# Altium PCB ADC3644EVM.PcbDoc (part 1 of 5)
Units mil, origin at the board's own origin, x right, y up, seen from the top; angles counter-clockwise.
Board outline 3900 x 2716.54 mil, 10 copper layers (Top Layer, L2 GND, L3 PWR, L4 GND, L5 SIG, L6 GND, L7 GND, L8 PWR, L9 GND, Bottom Layer), stack 61.2 mil thick; 368 components, 252 nets, 1539 pads, 1019 vias.
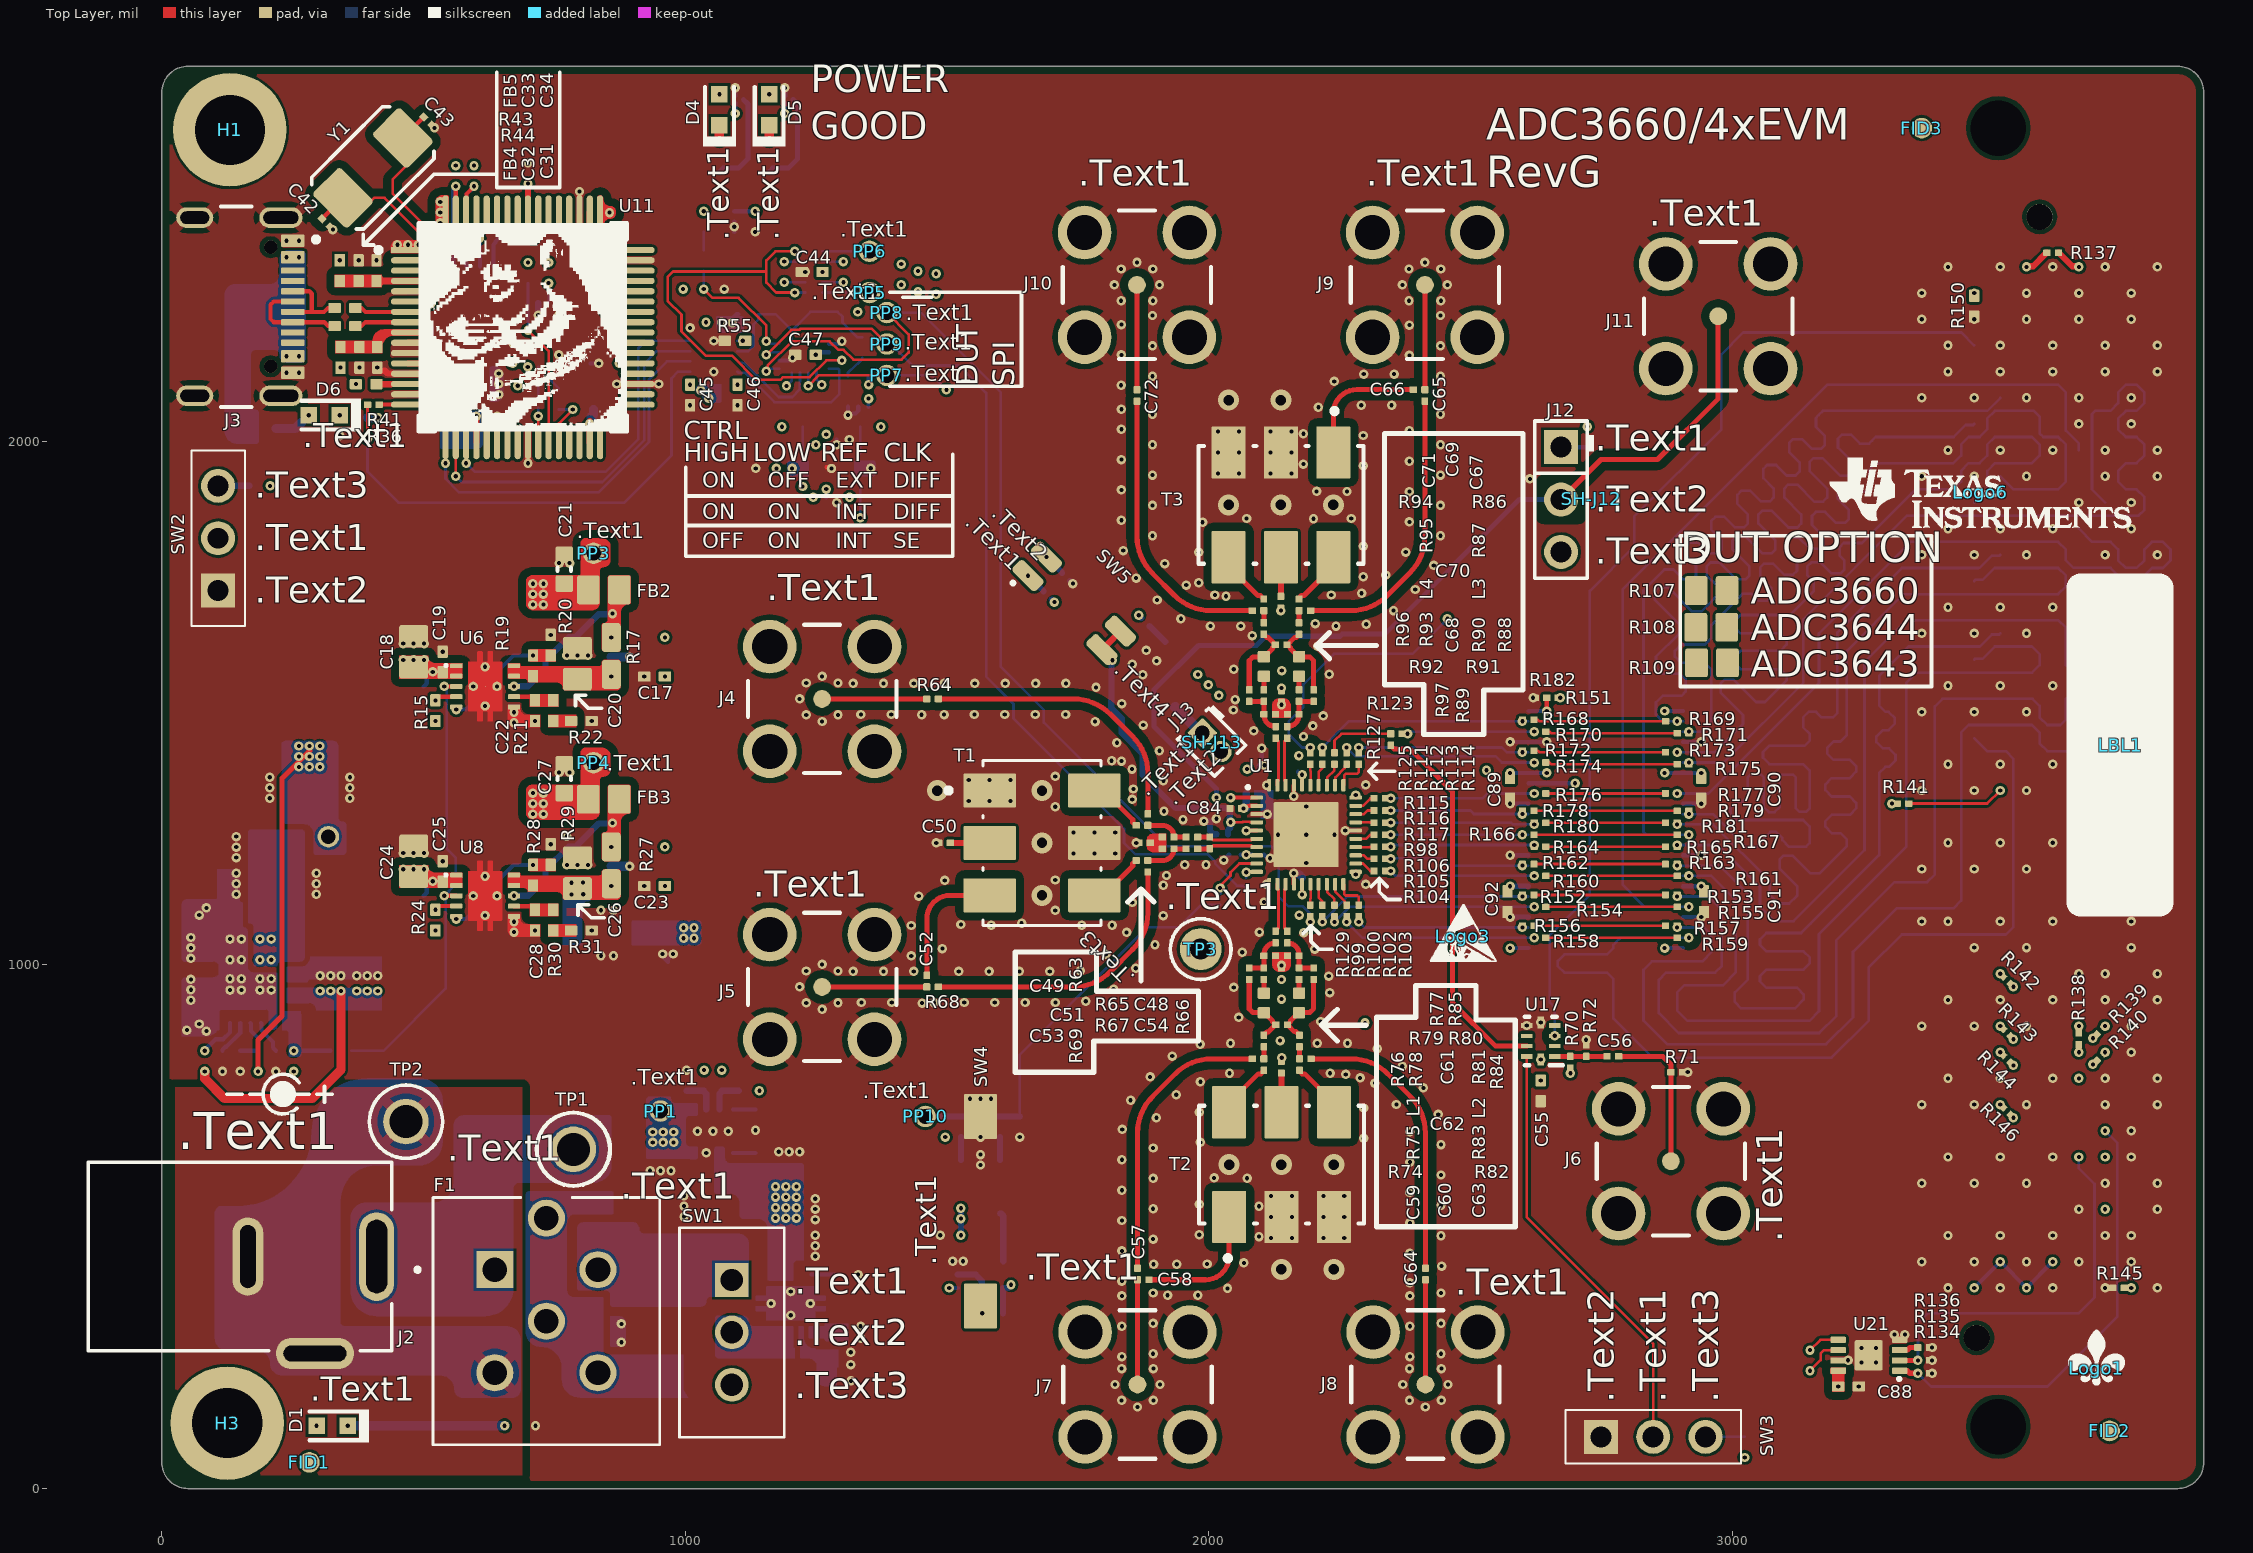
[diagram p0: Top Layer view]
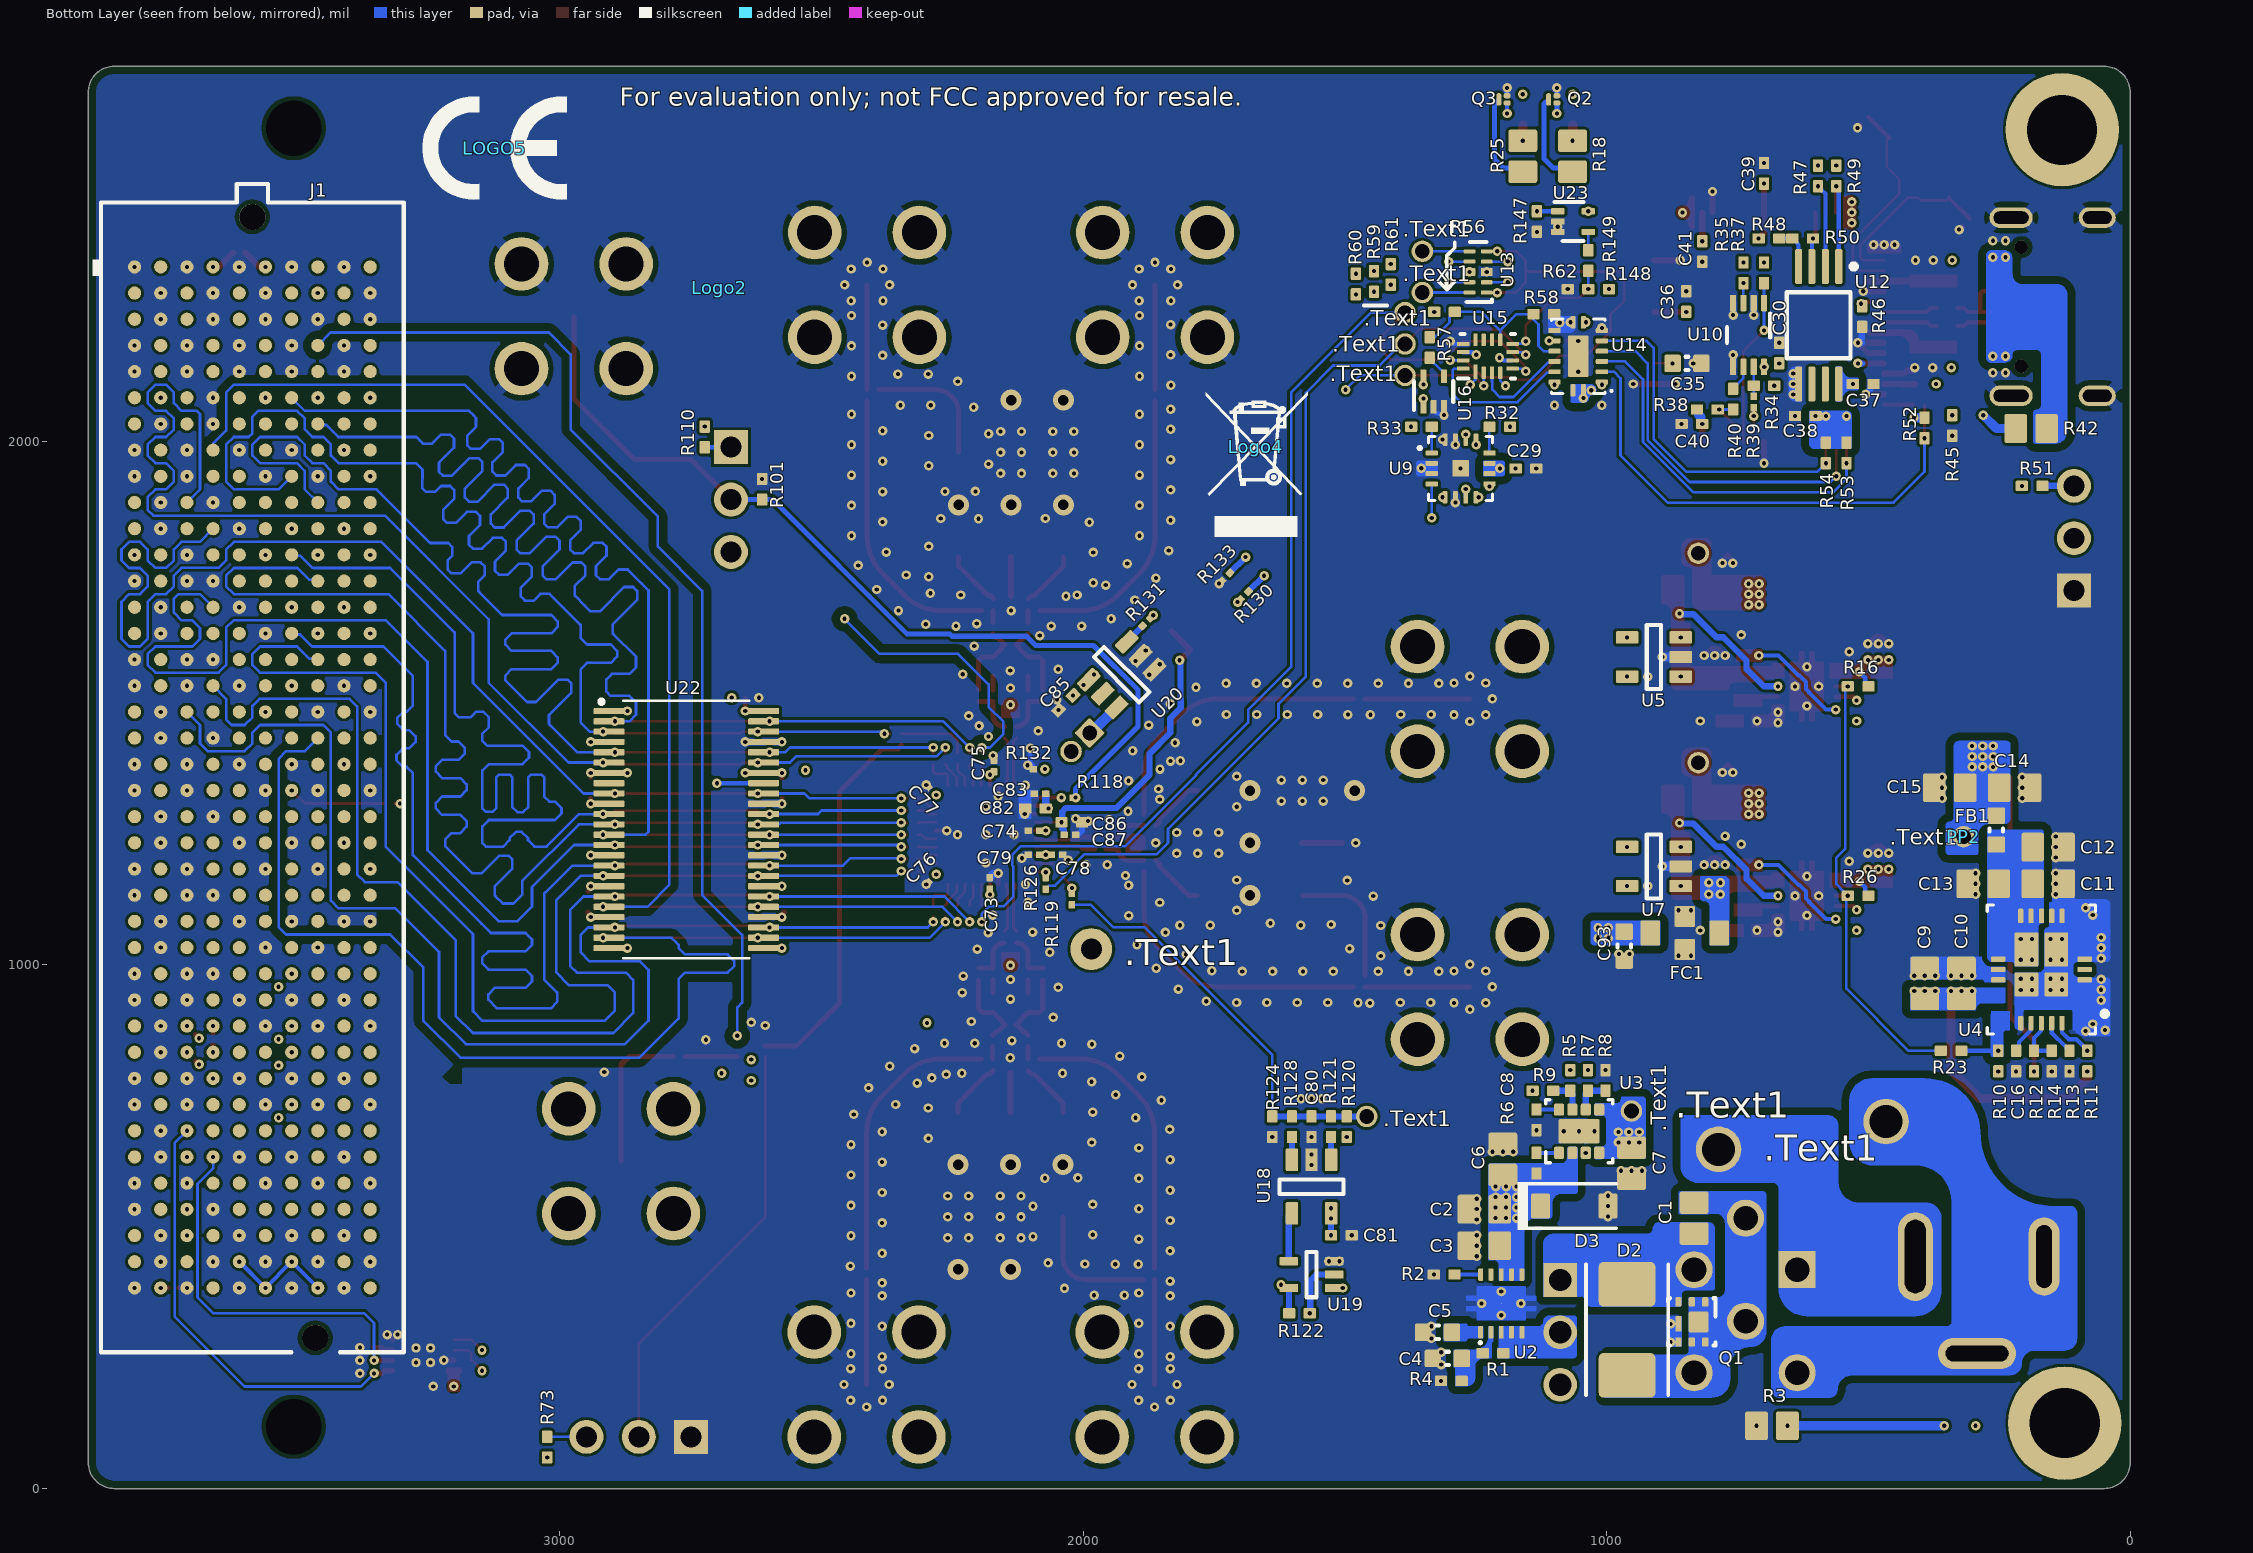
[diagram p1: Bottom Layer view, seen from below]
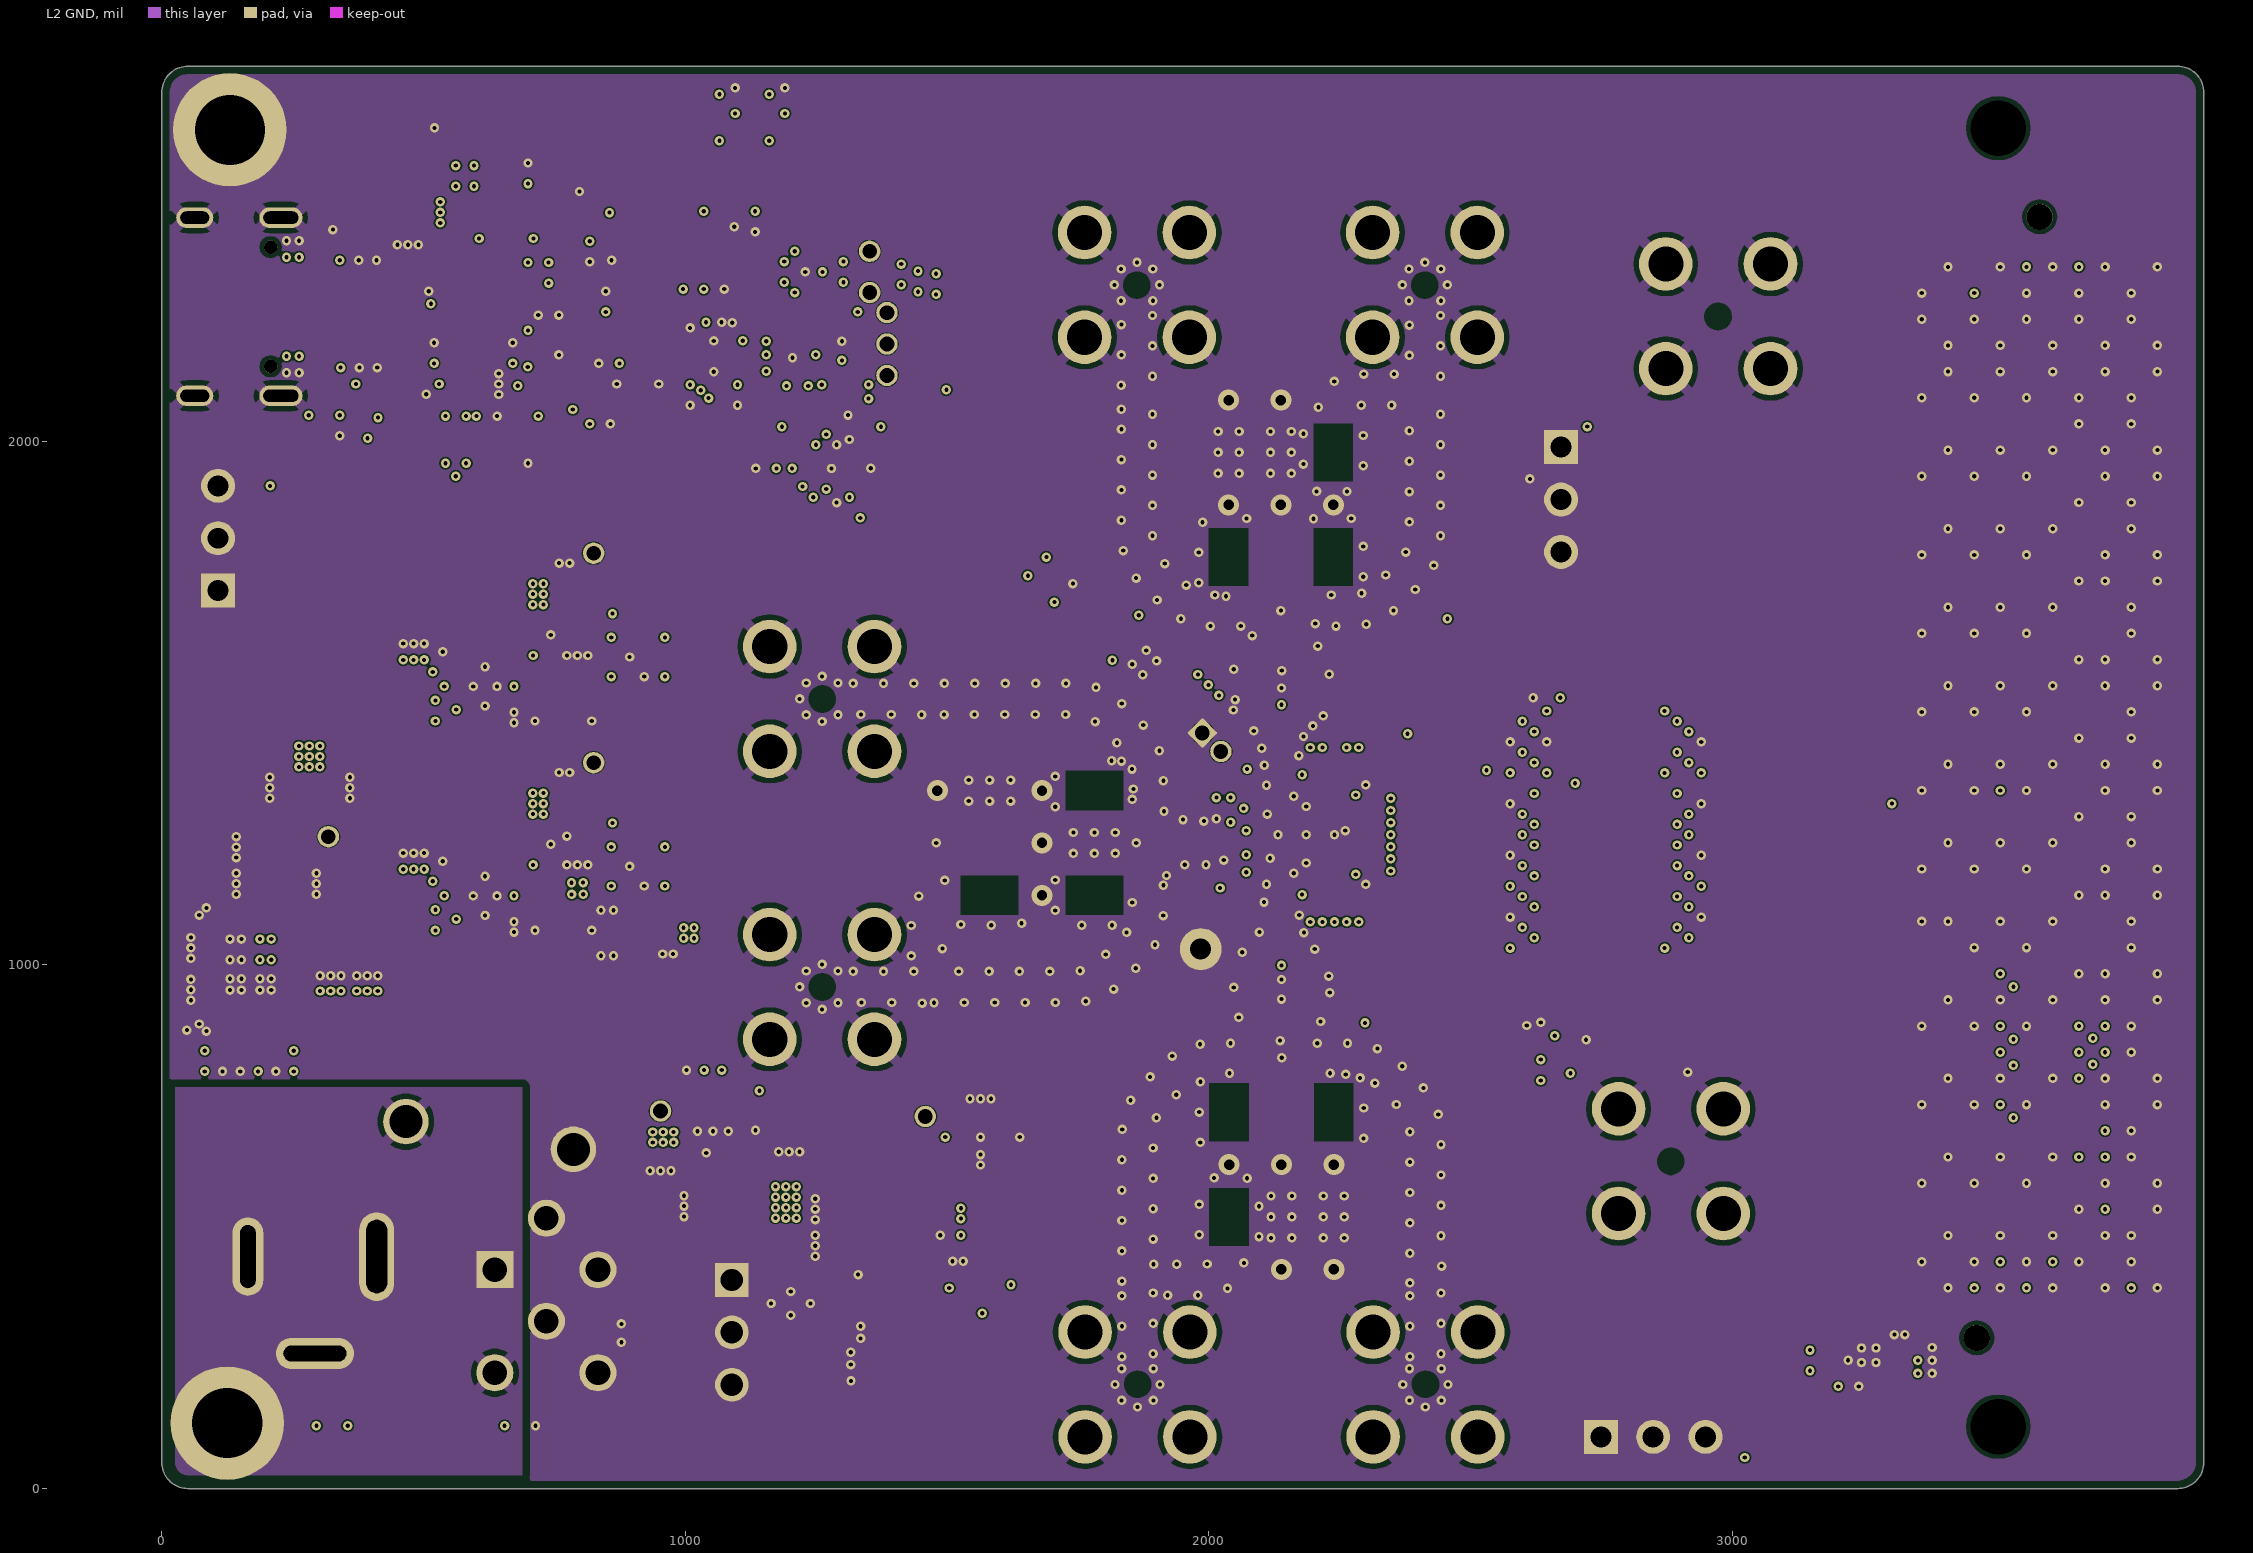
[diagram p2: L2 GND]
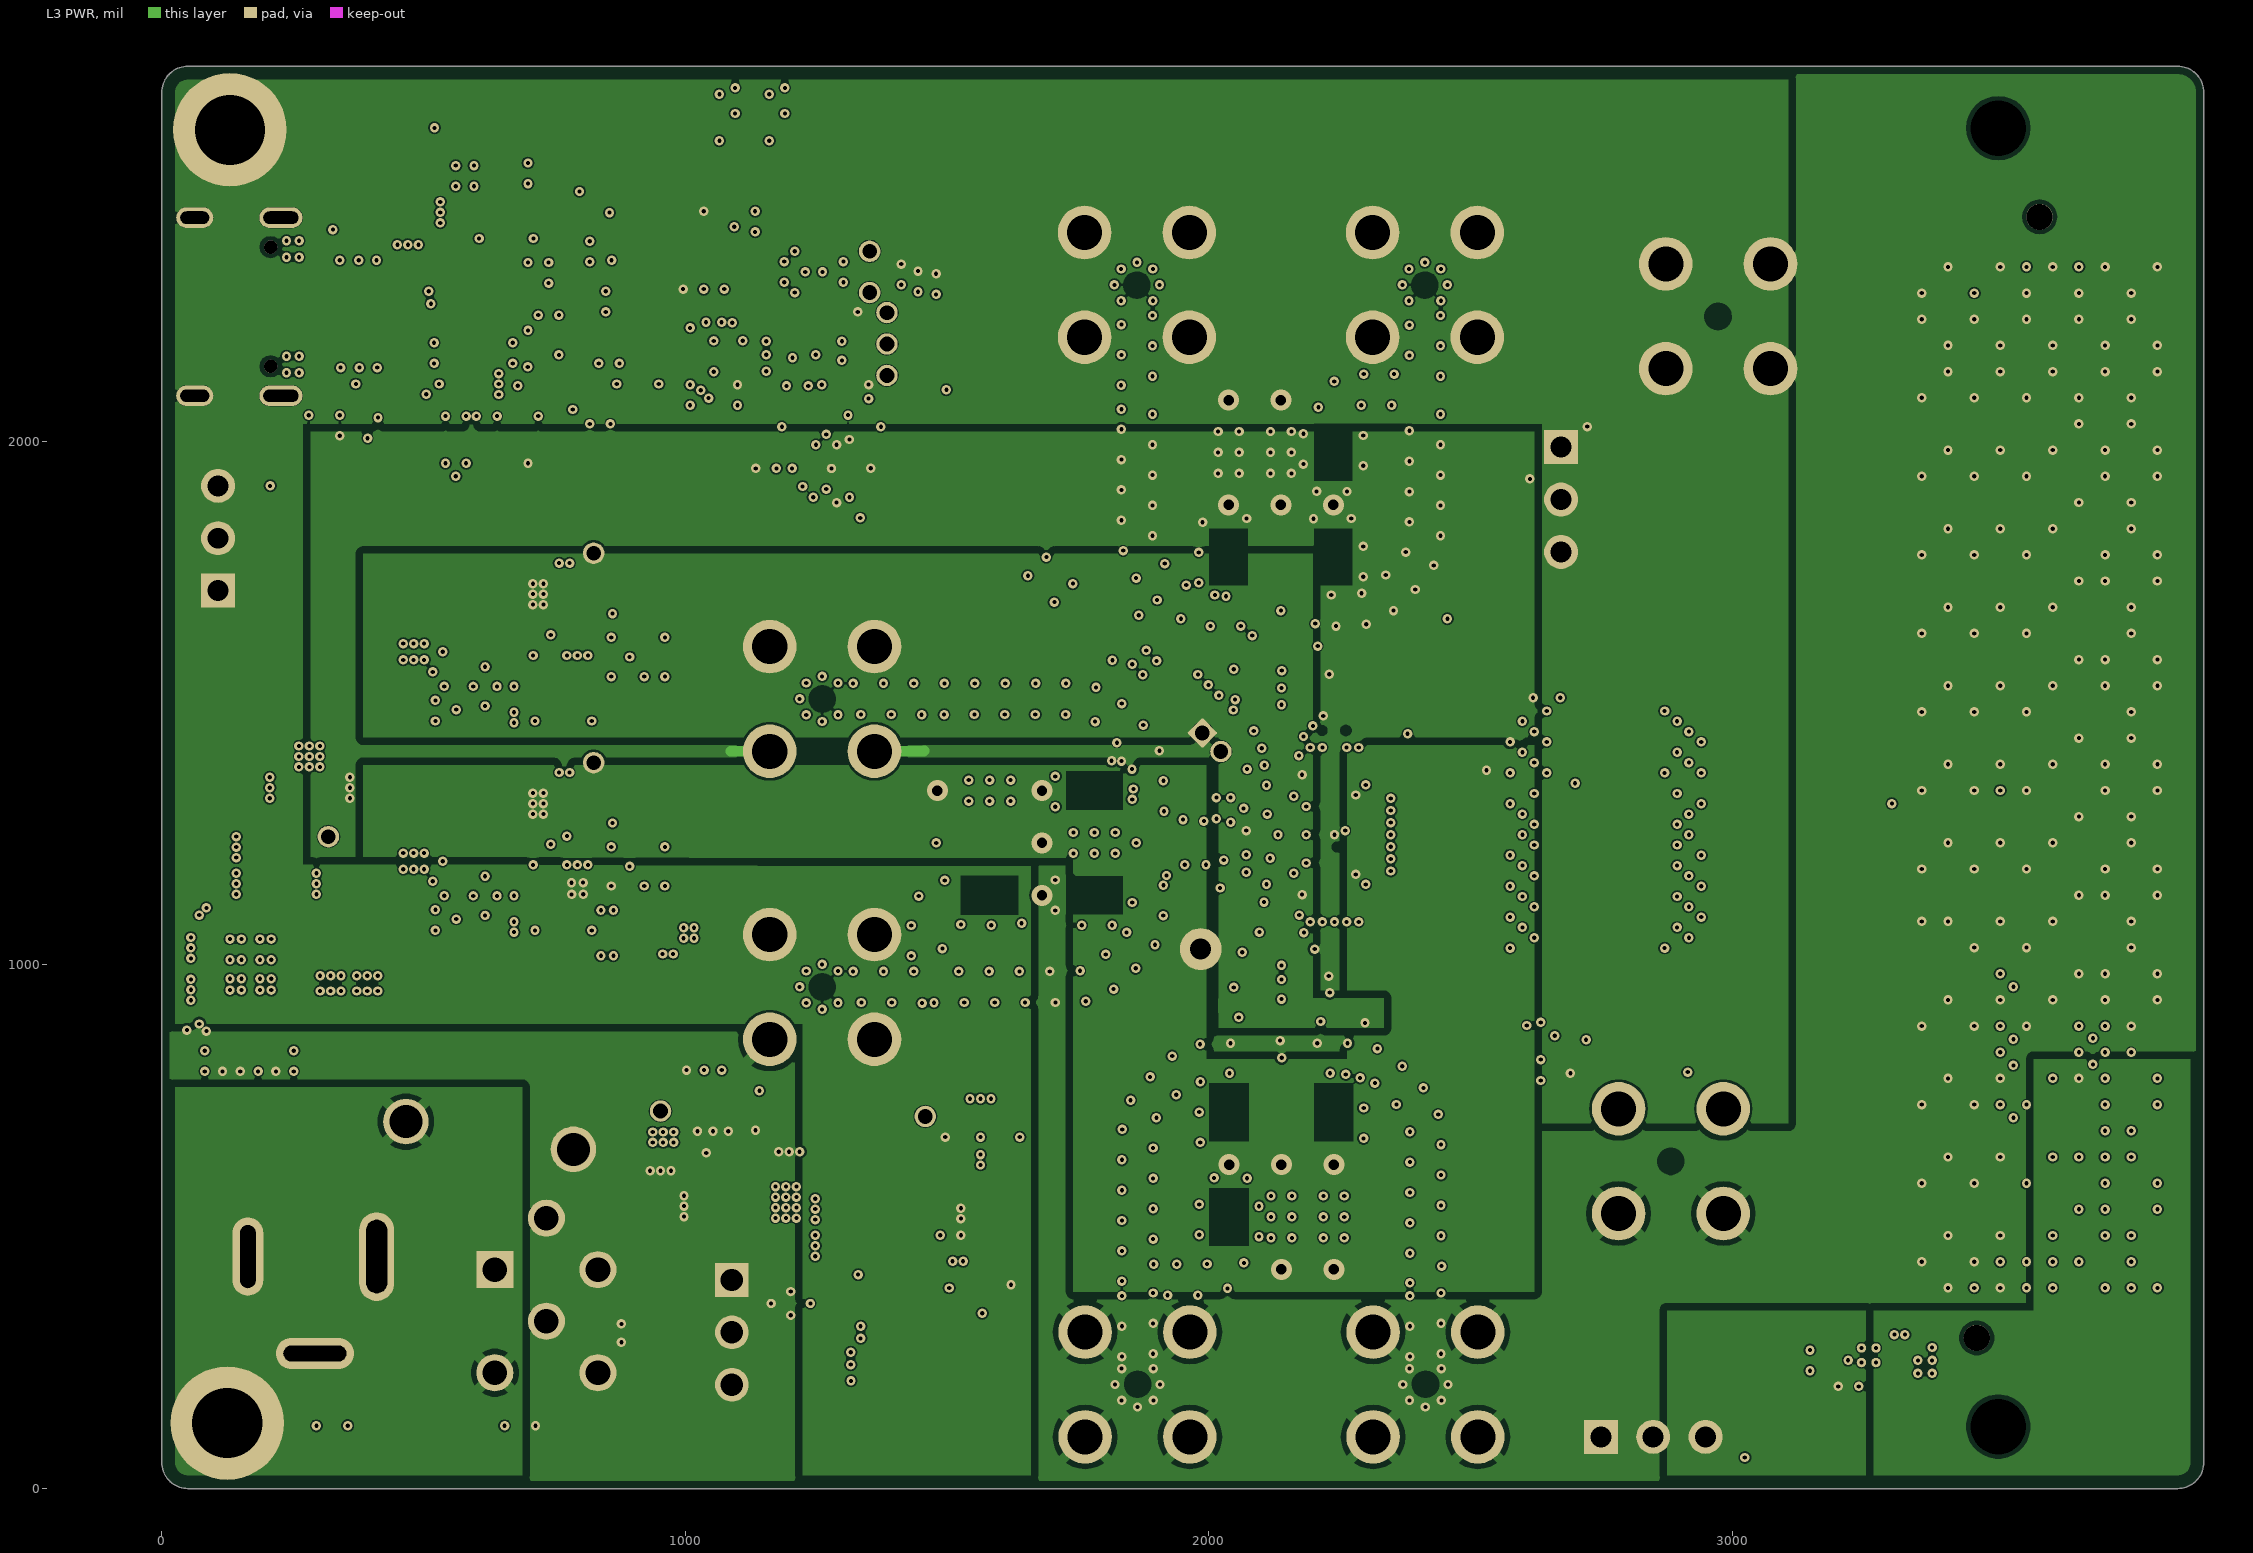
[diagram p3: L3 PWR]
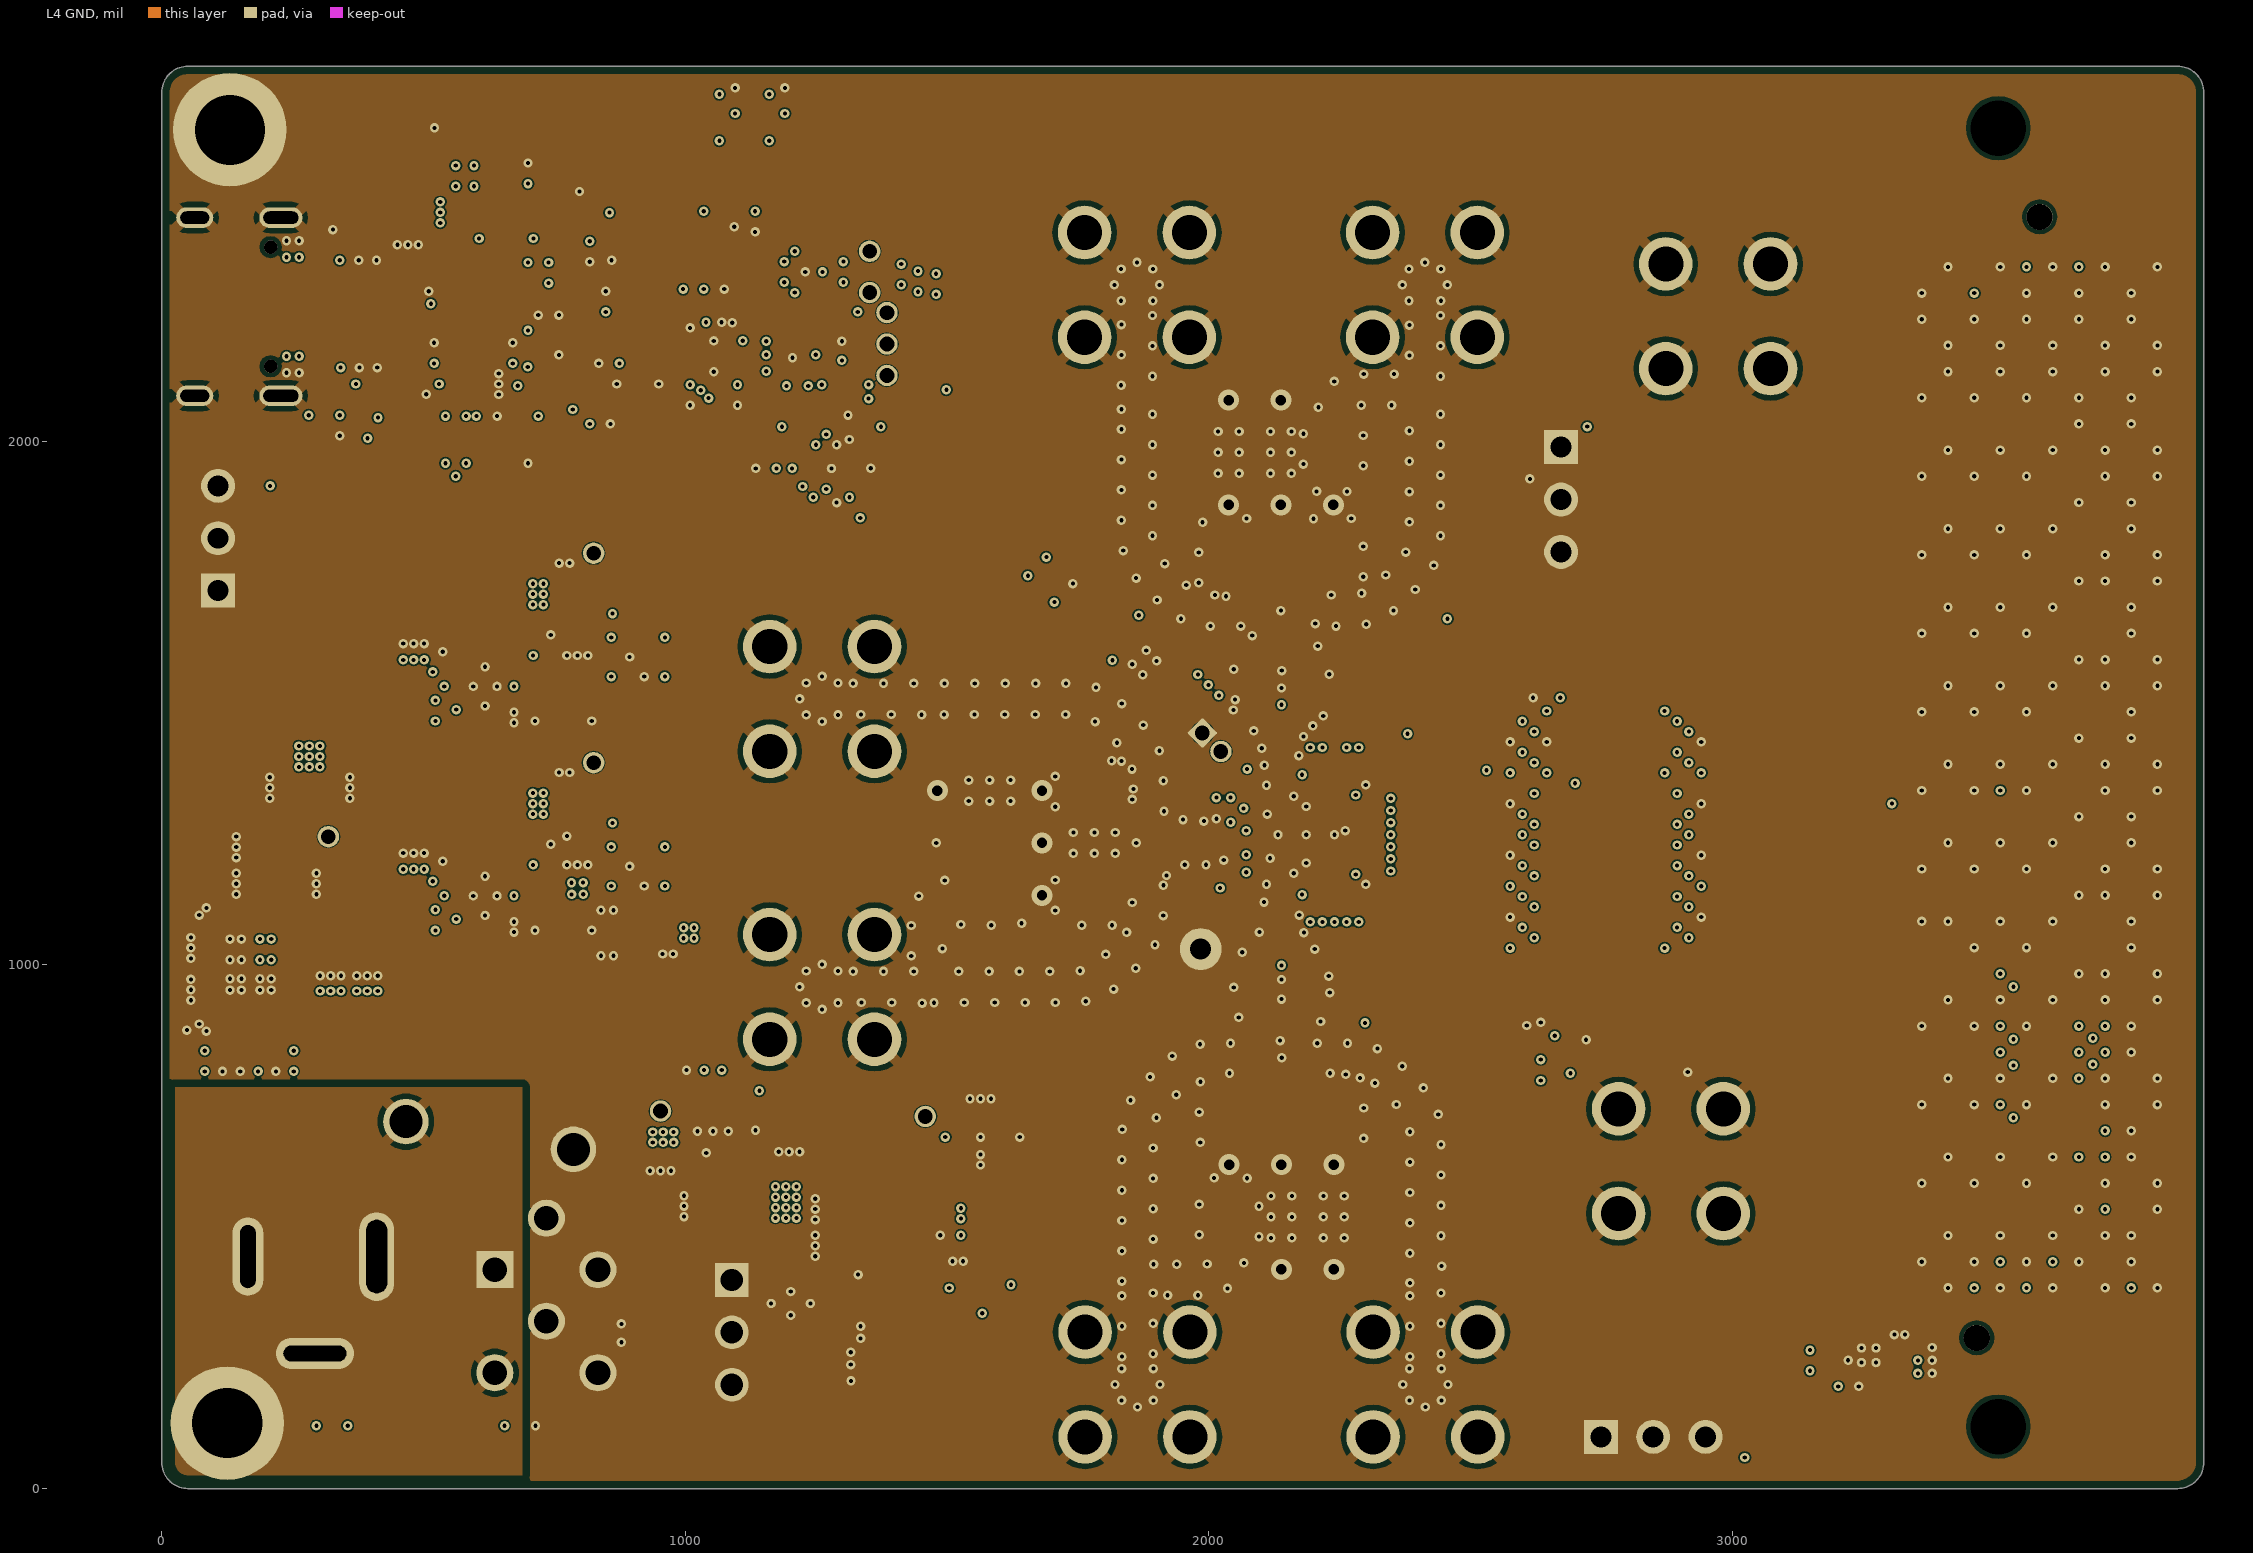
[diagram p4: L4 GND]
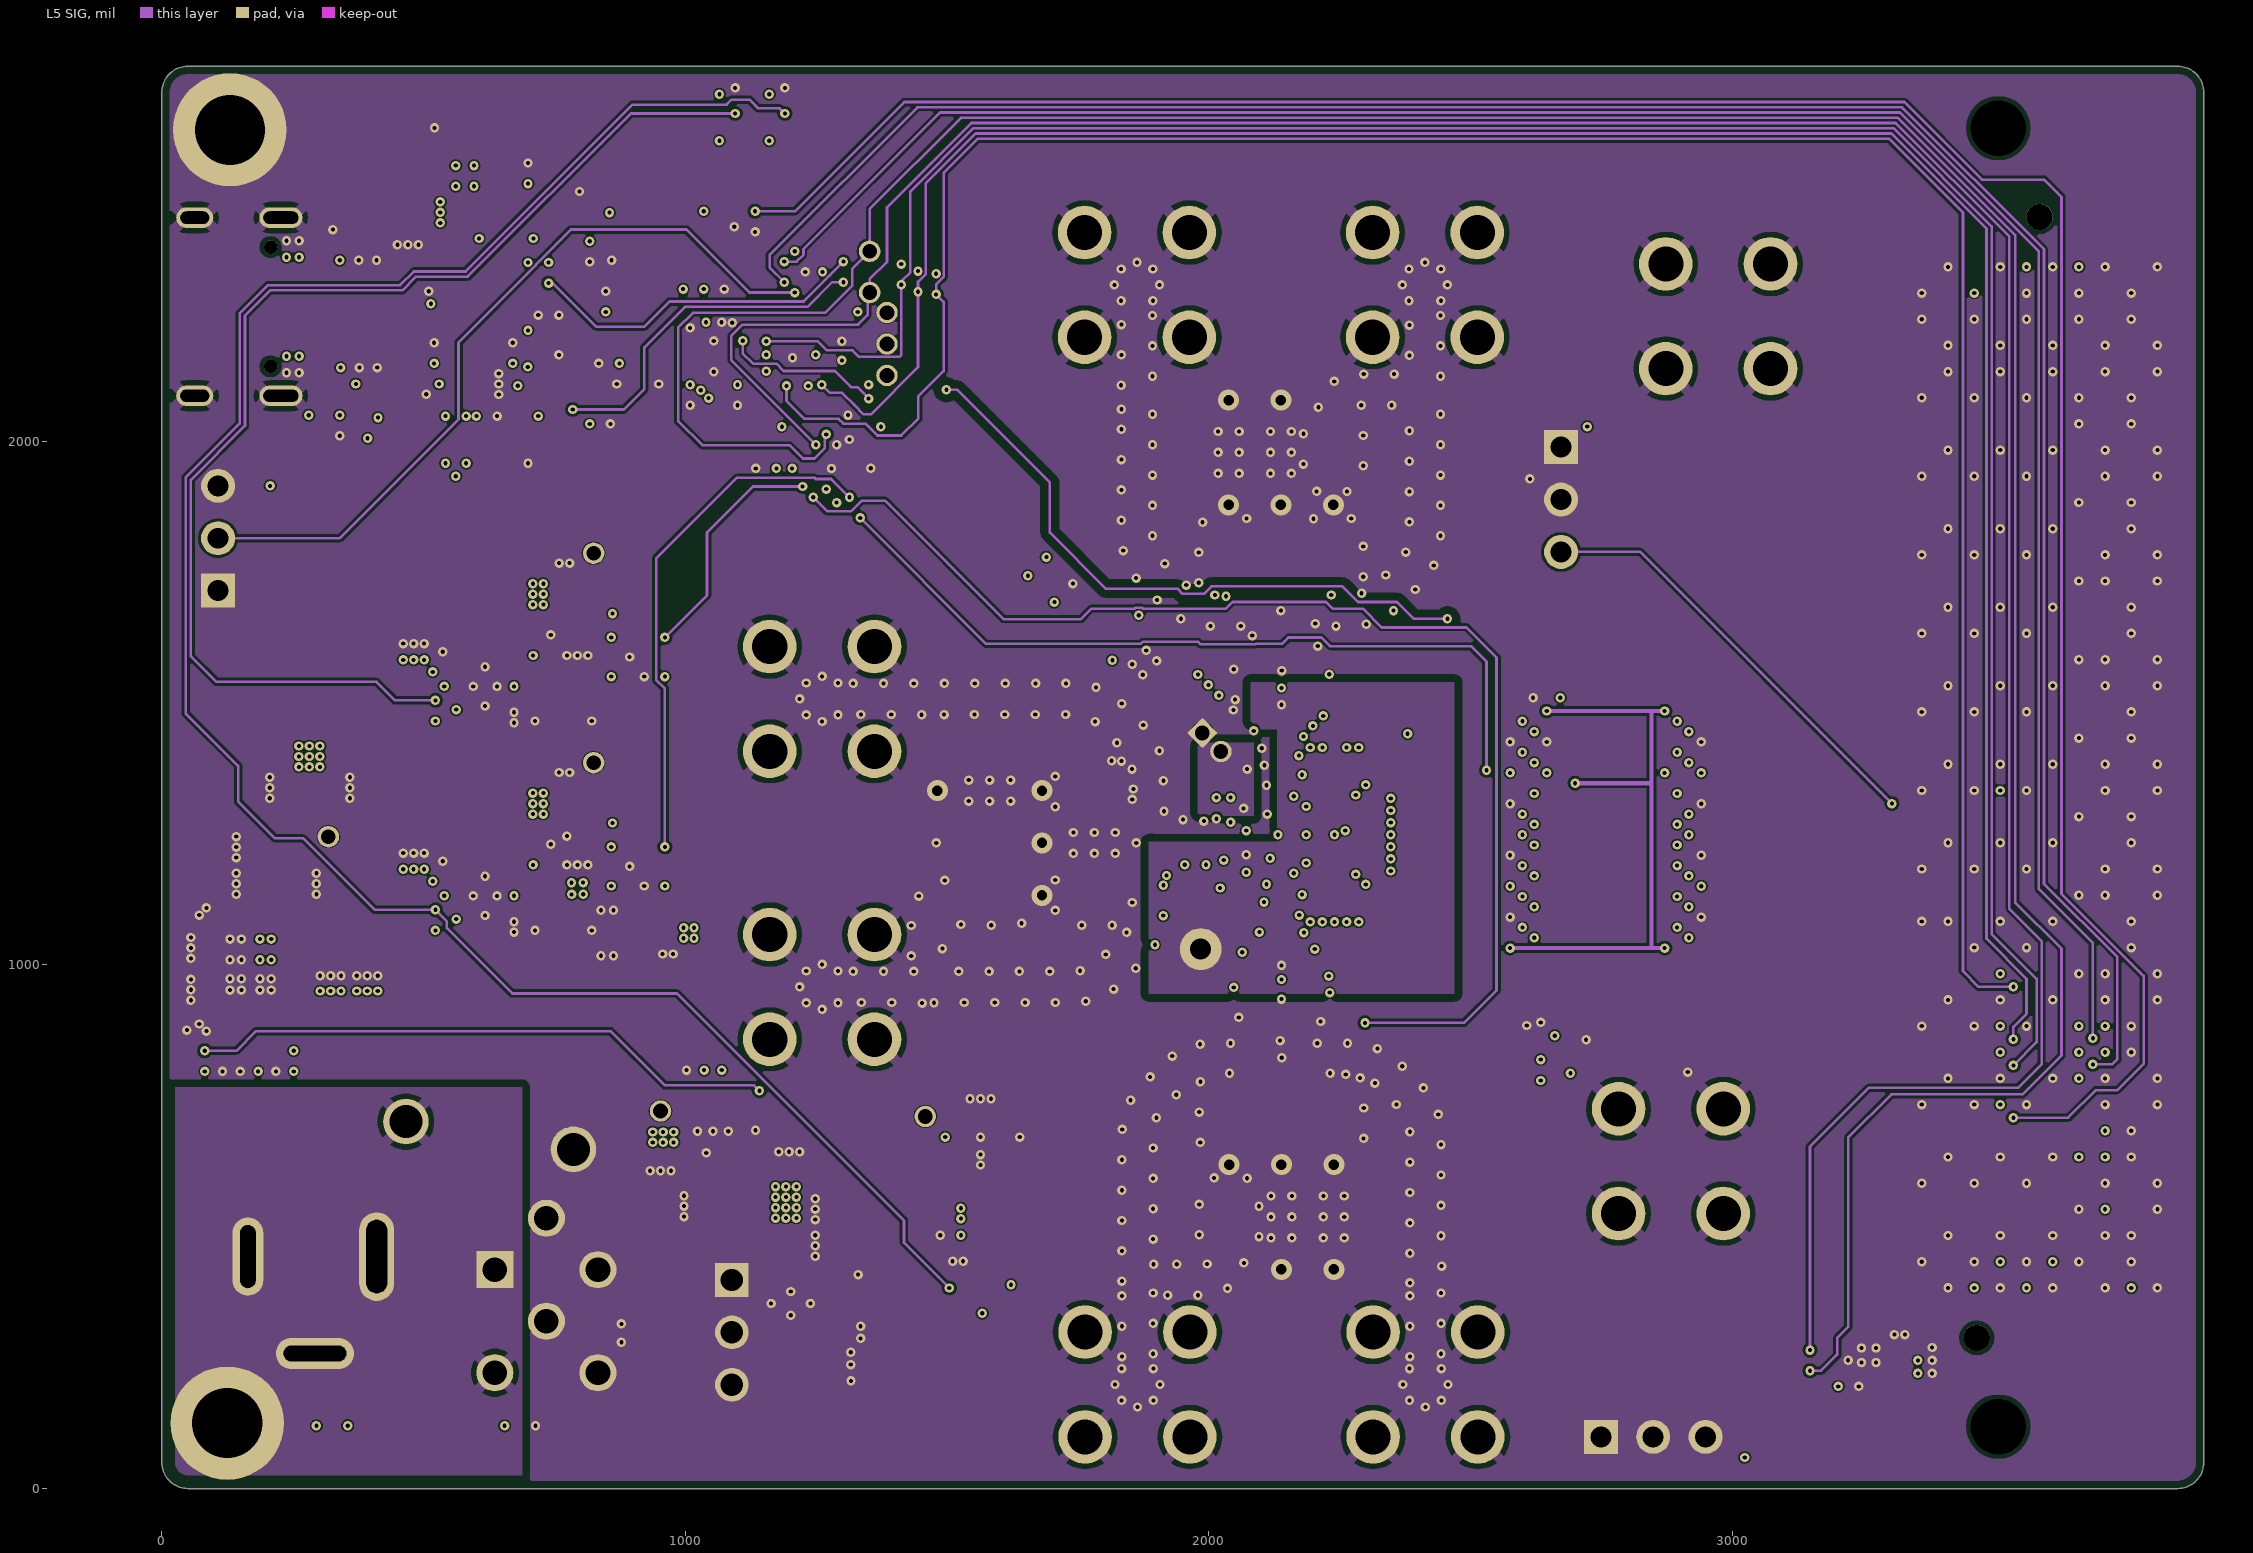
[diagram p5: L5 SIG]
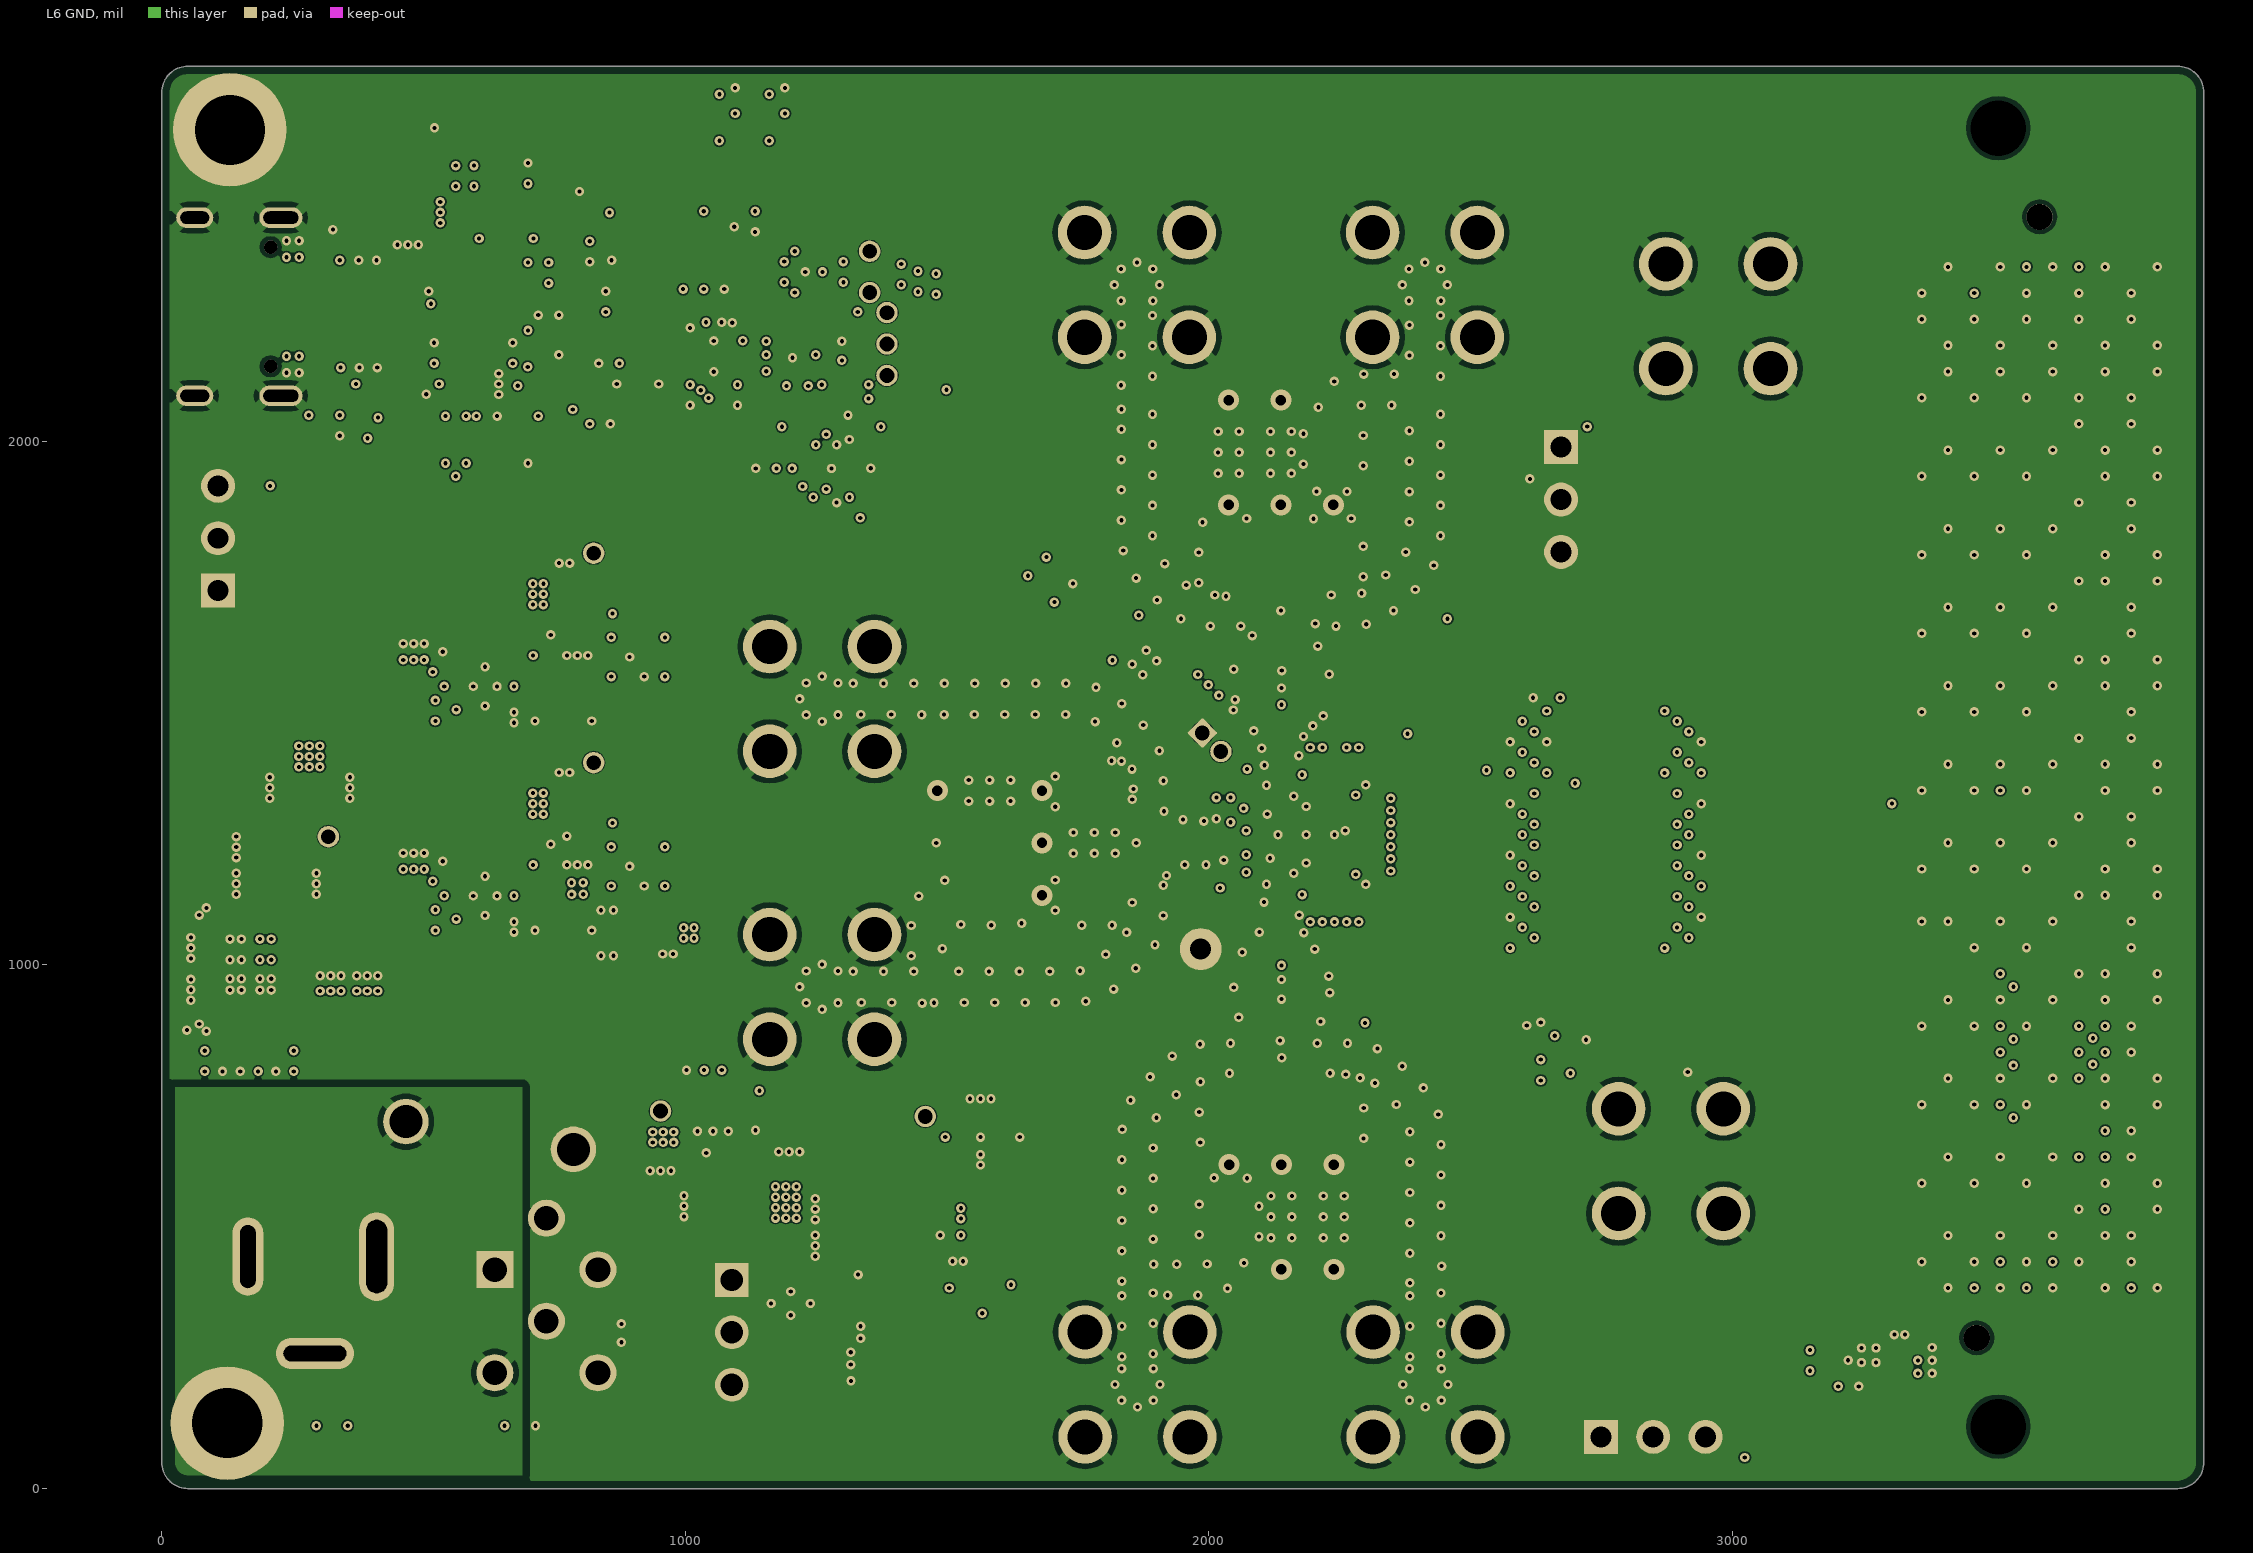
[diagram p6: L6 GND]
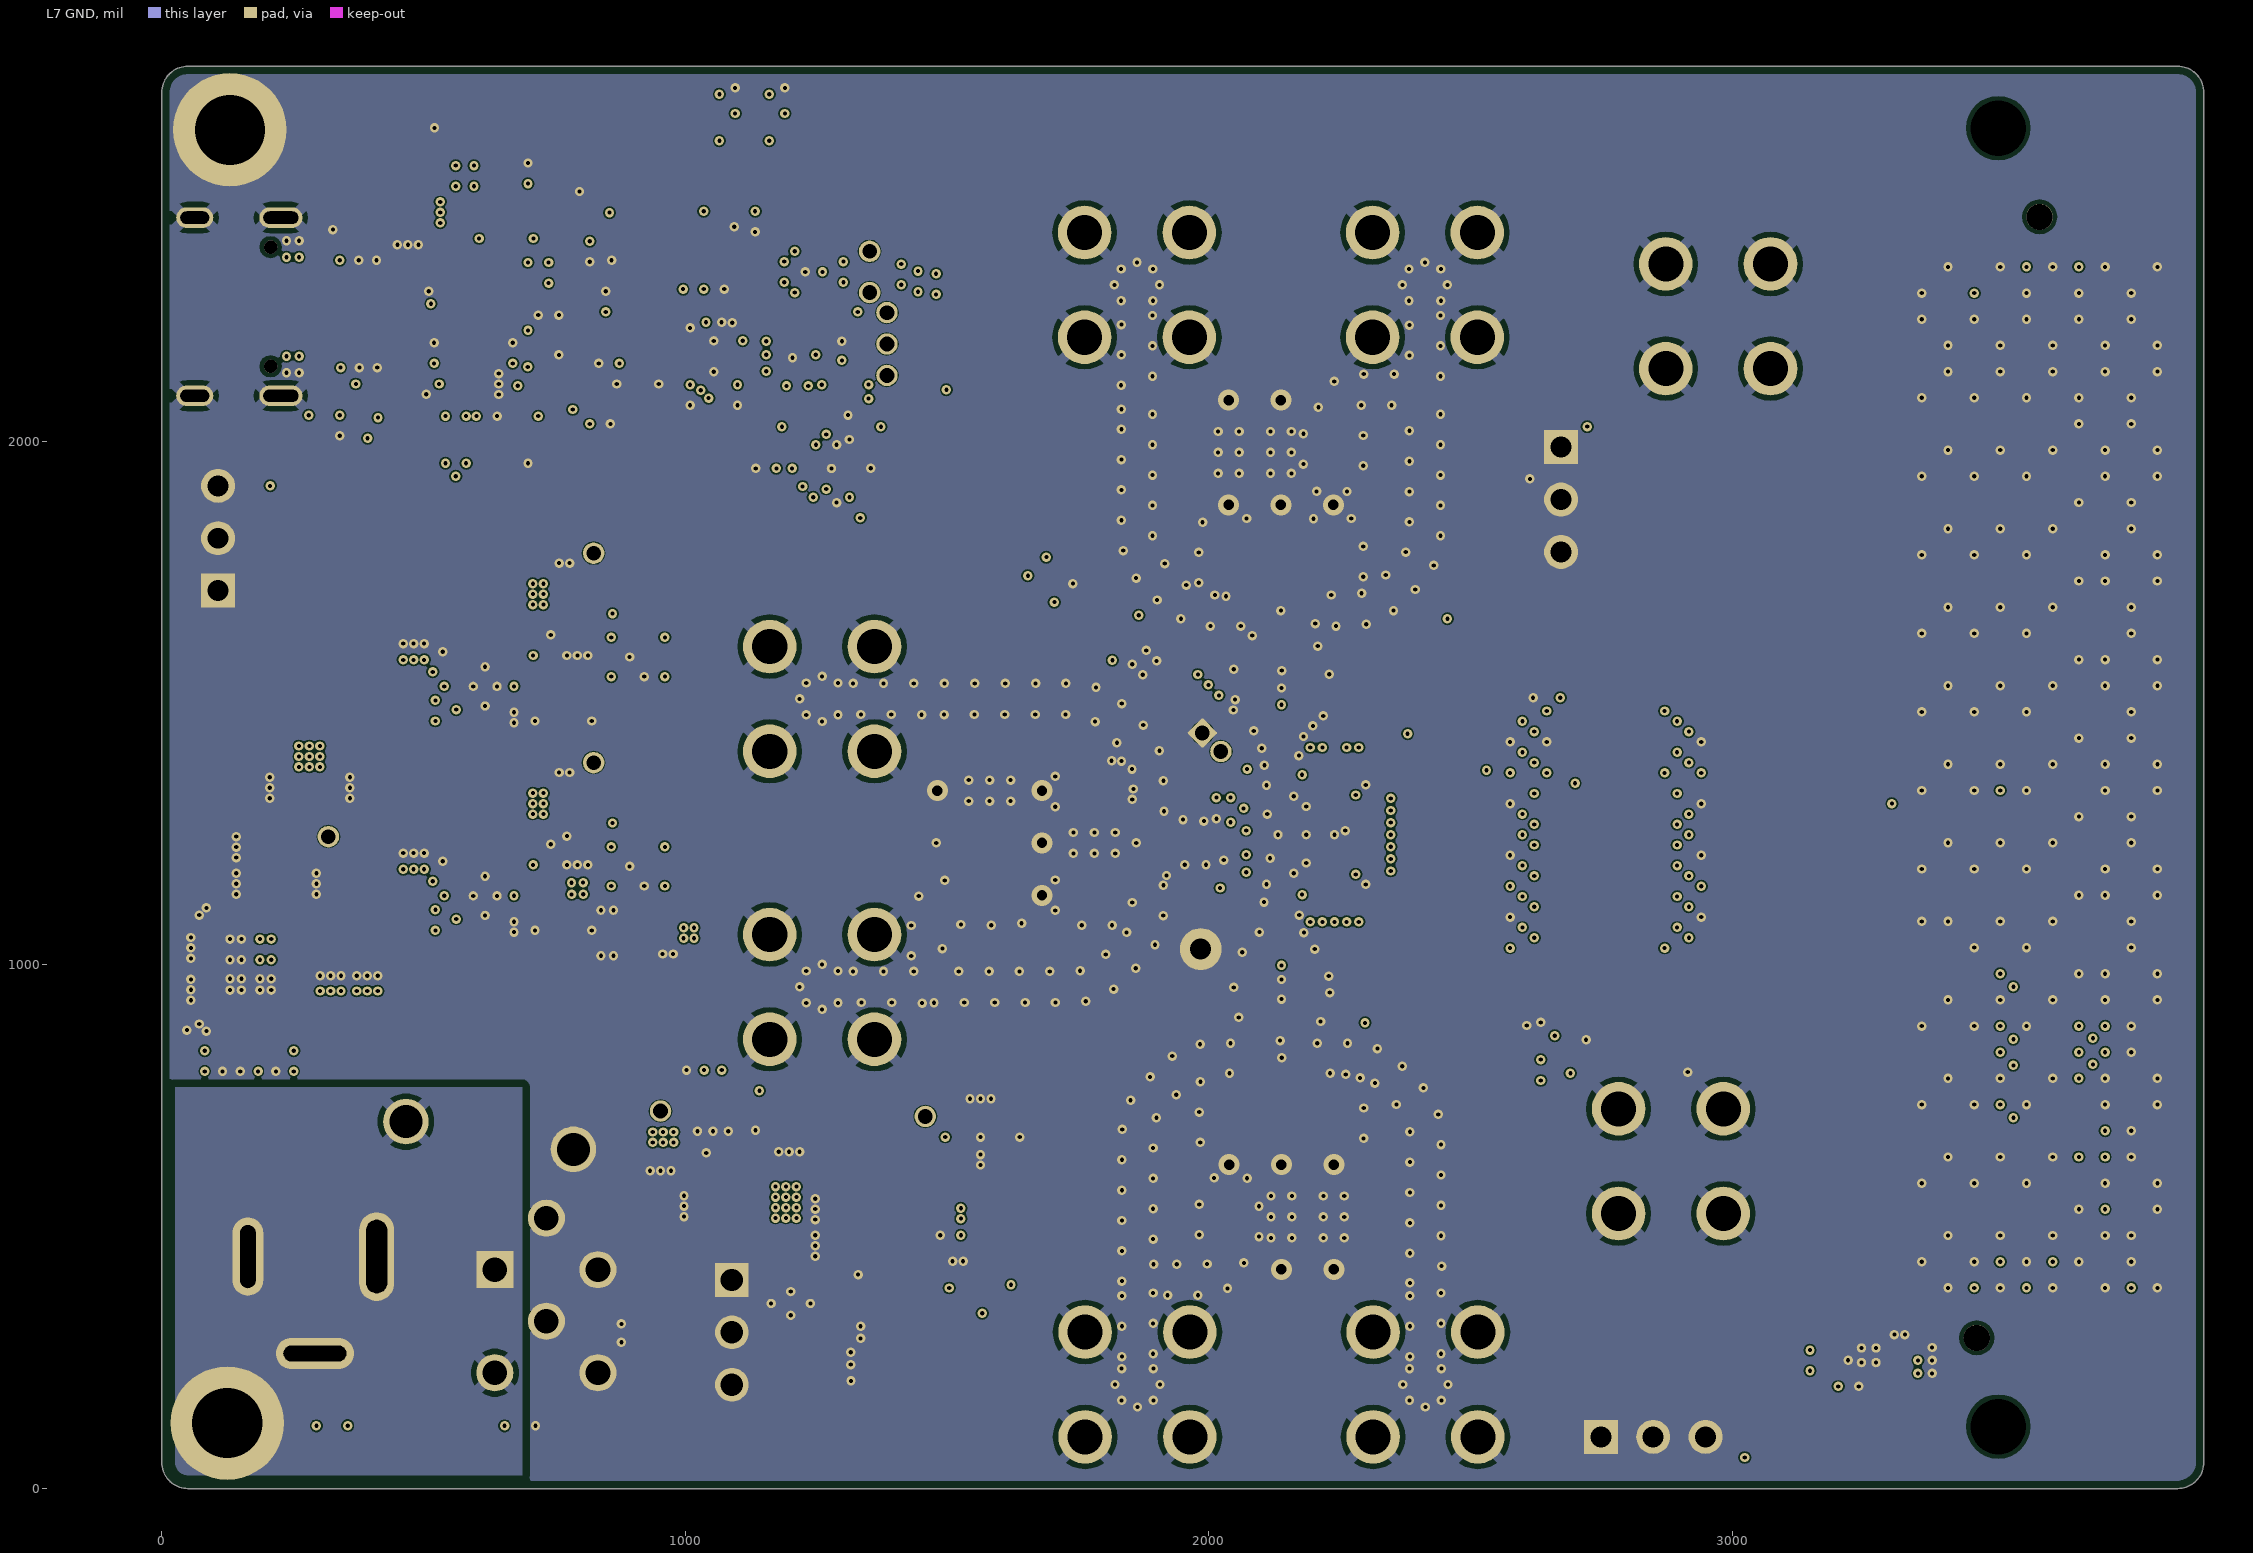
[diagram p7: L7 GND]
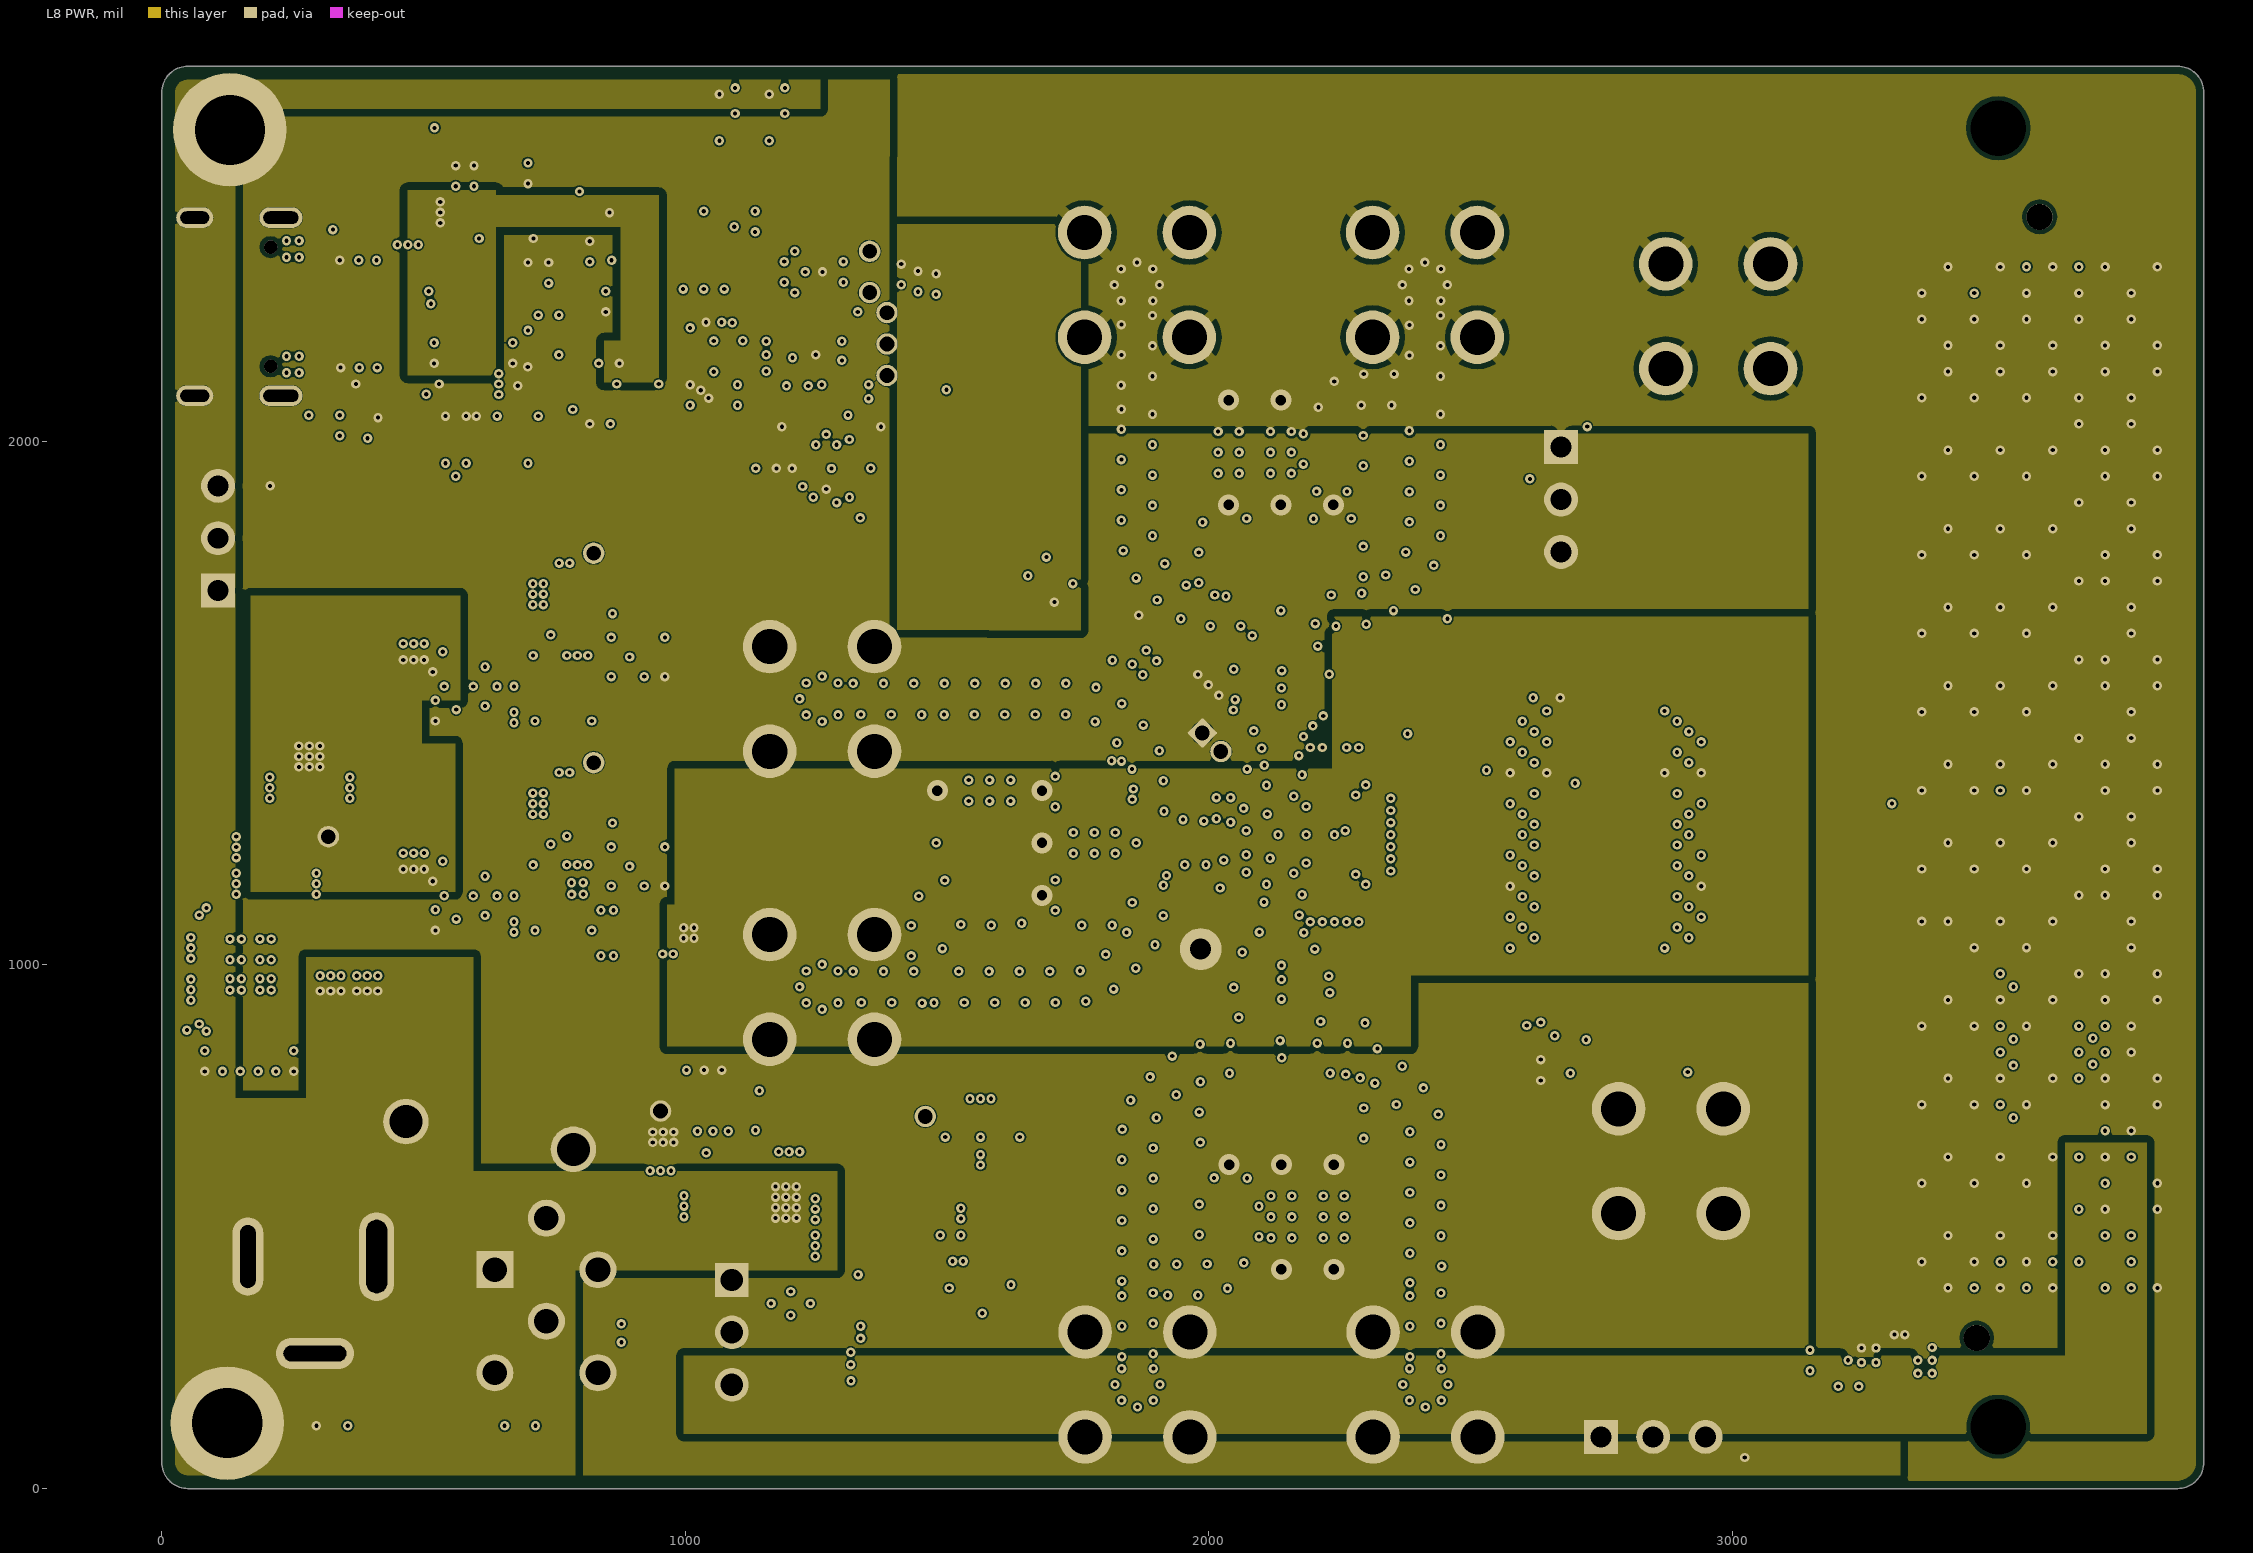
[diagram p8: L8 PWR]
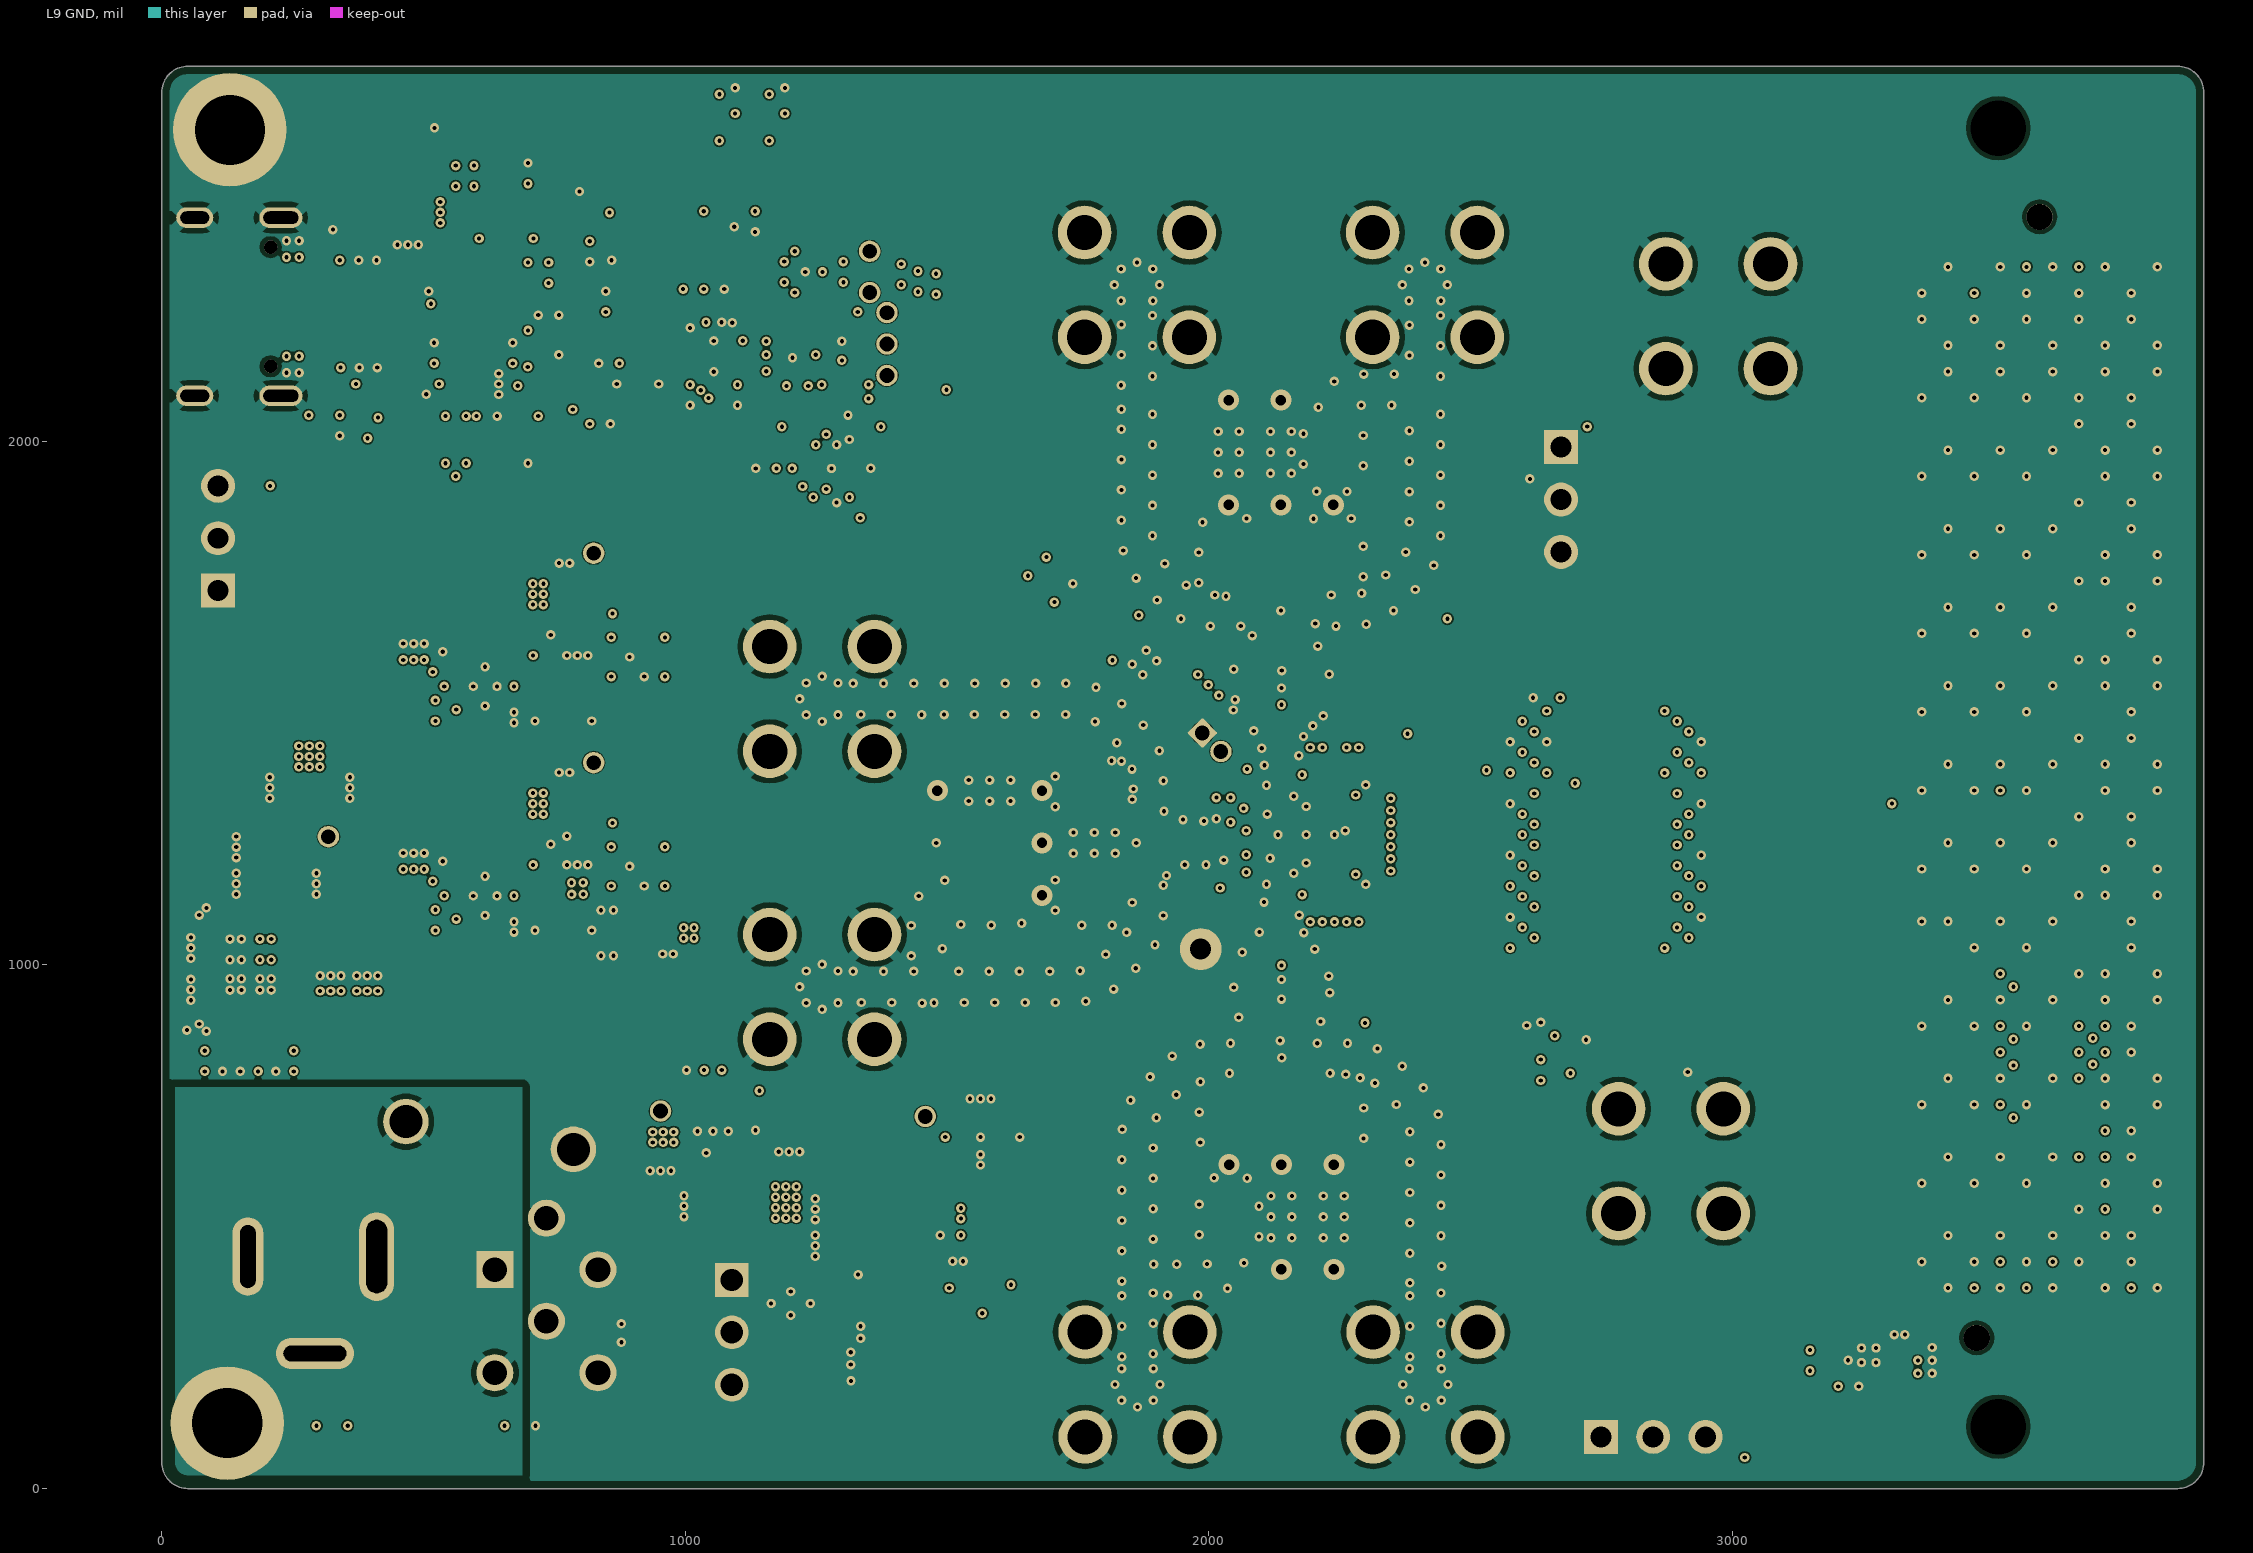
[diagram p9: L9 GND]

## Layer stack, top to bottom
Top Solder: solder mask 0.4, Solder Resist, Dk 3.5
Top Layer: signal copper 1.4
Dielectric 1: core 5, FR408HR, Dk 3.62
L2 GND: signal copper 1.4
Dielectric 3: prepreg 3.2, FR408HR, Dk 3.46
L3 PWR: signal copper 1.4
Dielectric 5: core 3, FR408HR, Dk 3.6
L4 GND: signal copper 1.4
Dielectric 7: prepreg 9.2, FR408HR, Dk 3.68
L5 SIG: signal copper 1.4
Dielectric1: prepreg 6.4, FR408HR, Dk 3.46
L6 GND: signal copper 1.4
Dielectric 8: prepreg 9.2, FR408HR, Dk 3.68
L7 GND: signal copper 1.4
Dielectric 6: core 3, FR408HR, Dk 3.6
L8 PWR: signal copper 1.4
Dielectric 4: prepreg 3.2, FR408HR, Dk 3.46
L9 GND: signal copper 1.4
Dielectric 2: core 5, FR408HR, Dk 3.62
Bottom Layer: signal copper 1.4
Bottom Solder: solder mask 0.4, Solder Resist, Dk 3.5

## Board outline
0,100 0,2666.54 cw(c50,2666.54) 50,2716.54 3850,2716.54 cw(c3850,2666.54) 3900,2666.54 3900,50 cw(c3850,50) 3850,0 50,0 cw(c50,50) 0,50

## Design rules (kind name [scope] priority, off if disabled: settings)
AcuteAngle [All] p1: minimum=4.50000000000000E+0001 checktracksonly=TRUE
AssemblyTestPointUsage [All] p1: valid=2
BoardOutlineClearance BoardOutlineClearance_Poly_LY2_GND [OnCopper and IsPoly and InNet('GND') and OnLayer('L2 GND')] p1 off: gap=25 ignorepadtopadclearanceinfootprint=FALSE except(0: Poly-OutlineEdge)
BoardOutlineClearance BoardOutlineClearance_Poly_GND [OnCopper and IsPoly and InNet('GND')] p2: gap=15 ignorepadtopadclearanceinfootprint=FALSE // for poly ground to edge on layer 2 and less pullback on other layers
BoardOutlineClearance BoardOutlineClearance_MountingHoles [OnCopper and InComponentClass('Mounting Holes')] p3: gap=39.37 ignorepadtopadclearanceinfootprint=FALSE
BoardOutlineClearance BoardOutlineClearance_Poly [OnCopper and IsPoly] p4: gap=25 ignorepadtopadclearanceinfootprint=FALSE // for non-ground polygons pull back
BoardOutlineClearance [OnCopper and Not InComponentClass('Logo') and not InComponentClass('FiducialMark') and not InRegion(1000,500,4000,800) and not InPoly and not HasFootprint('cbts130a')] p5: gap=25 ignorepadtopadclearanceinfootprint=FALSE
Clearance Clearance-CMOS [InNetClass('CMOS_BUF_Out') vs HasFootprint('SAMTEC_ASP-134488-01')] p1: gap=5 ignorepadtopadclearanceinfootprint=TRUE except(8: Arc-Hole Track-Hole SMDPad-Hole THPad-Hole Via-Hole Fill-Hole Poly-Hole Region-Hole Text-Hole; 9.9: Arc-SMDPad Track-SMDPad; 10: SMDPad-SMDPad THPad-Fill THPad-Poly THPad-Region; 15: Arc-Fill Arc-Poly Arc-Region Track-Fill Track-Poly Track-Region Fill-Fill Fill-Poly Fill-Region Poly-Poly Poly-Region Region-Region)
Clearance Clearance_Poly_GND [InPolygon and InNet('GND')] p2: gap=5 ignorepadtopadclearanceinfootprint=TRUE except(8: Arc-Hole Track-Hole SMDPad-Hole THPad-Hole Via-Hole Fill-Hole Poly-Hole Region-Hole Text-Hole; 15: Fill-Fill Fill-Poly Fill-Region Poly-Poly Poly-Region Region-Region)
Clearance Clearance_Keepouts [((IsTrack Or IsArc) And Not InPoly) And IsFree and IsKeepOut vs ((IsTrack Or IsArc) And Not InPoly) And IsFree and IsKeepOut] p3: gap=0 ignorepadtopadclearanceinfootprint=FALSE
Clearance Clearance_Poly [InPolygon] p4: gap=5 ignorepadtopadclearanceinfootprint=TRUE except(8: Arc-Hole Track-Hole SMDPad-Hole THPad-Hole Via-Hole Fill-Hole Poly-Hole Region-Hole Text-Hole; 15: Fill-Fill Fill-Poly Fill-Region Poly-Poly Poly-Region Region-Region)
Clearance Clearance_FiducialMark [IsKeepOut and InComponentClass('FiducialMark') vs IsPad and InComponentClass('FiducialMark')] p5: gap=0 ignorepadtopadclearanceinfootprint=FALSE
Clearance Clearance_Outter_Layers [All vs OnLayer('Top Layer') or OnLayer('Bottom Layer') and not InAnyDifferentialPair] p6: gap=5 ignorepadtopadclearanceinfootprint=TRUE except(4: Arc-Arc Arc-Track Track-Track; 4.25: SMDPad-Via; 8: Arc-Hole Track-Hole SMDPad-Hole THPad-Hole Via-Hole Fill-Fill Fill-Poly Fill-Region Fill-Hole Poly-Poly Poly-Region Poly-Hole Region-Region Region-Hole Text-Hole; 10: SMDPad-SMDPad THPad-Fill THPad-Poly THPad-Region)
Clearance Clearance_Inner_Layers [All vs not OnLayer('Top Layer') and not OnLayer('Bottom Layer') and not InAnyDifferentialPair] p7: gap=5 ignorepadtopadclearanceinfootprint=TRUE except(8: Arc-Hole Track-Hole SMDPad-Hole THPad-Hole Via-Hole Fill-Hole Poly-Hole Region-Hole Text-Hole; 10: SMDPad-SMDPad THPad-Fill THPad-Poly THPad-Region; 15: Arc-Fill Arc-Poly Arc-Region Track-Fill Track-Poly Track-Region Fill-Fill Fill-Poly Fill-Region Poly-Poly Poly-Region Region-Region)
ComponentClearance "ComponentClearance Part Overlap" [All] p1: gap=0 collisioncheckmode=3 verticalgap=0 showdistances=FALSE
ComponentClearance ComponentClearance_MountingHoles_FiducialMarks [InComponentClass('Mounting Holes') vs InComponentClass('FiducialMark')] p2: gap=50 collisioncheckmode=3 verticalgap=10 showdistances=FALSE
ComponentClearance ComponentClearance_Shunt [InComponentClass('Header') vs InComponentClass('Shunt')] p3: gap=0 collisioncheckmode=3 verticalgap=0 showdistances=FALSE
ComponentClearance ComponentClearance_Logo [InComponentClass('Logo')] p4: gap=50 collisioncheckmode=3 verticalgap=10 showdistances=FALSE
ComponentClearance ComponentClearance_ScrewToNut [(HasFootprint('NY PMS 440 0025 PH')) vs (HasFootprint('Keystone_1902C'))] p5: gap=5 collisioncheckmode=3 verticalgap=10 showdistances=FALSE
ComponentClearance ComponentClearance_MountingHoles [InComponentClass('Mounting Holes')] p6: gap=100 collisioncheckmode=3 verticalgap=100000 showdistances=FALSE
ComponentClearance ComponentClearance_SmallPassives [HasFootprint('0201*') or HasFootprint('0402*') or HasFootprint('0508') or HasFootprint('0603*') or HasFootprint('0612') or HasFootprint('0805*') or HasFootprint('0815*') or HasFootprint('0830*') or HasFootprint('1206*') or HasFootprint('1210*') or HasFootprint('1808*') or HasFootprint('1812*') or HasFootprint('1825*') or HasFootprint('2010*') or HasFootprint('2220*') or HasFootprint('2225*') or HasFootprint('2512*') or HasFootprint('2728*') or HasFootprint('3518*') vs HasFootprint('0201*') or HasFootprint('0402*') or HasFootprint('0508') or HasFootprint('0603*') or HasFootprint('0612') or HasFootprint('0805*') or HasFootprint('0815*') or HasFootprint('0830*') or HasFootprint('1206*') or HasFootprint('1210*') or HasFootprint('1808*') or HasFootprint('1812*') or HasFootprint('1825*') or HasFootprint('2010*') or HasFootprint('2220*') or HasFootprint('2225*') or HasFootprint('2512*') or HasFootprint('2728*') or HasFootprint('3518*')] p7: gap=10 collisioncheckmode=3 verticalgap=10 showdistances=FALSE
ComponentClearance ComponentClearance_THtoSMT [IsThruComponent and not HasFootprint('ProbePoint_TH_40mil') vs IsSMTComponent] p8: gap=20 collisioncheckmode=3 verticalgap=0 showdistances=FALSE
ComponentClearance ComponentClearance_THtoTH [IsThruComponent and not HasFootprint('ProbePoint_TH_40mil') vs IsThruComponent and not HasFootprint('ProbePoint_TH_40mil')] p9: gap=30 collisioncheckmode=3 verticalgap=30 showdistances=FALSE
ComponentClearance [All] p10: gap=10 collisioncheckmode=3 verticalgap=10 showdistances=FALSE
DiffPairsRouting [All] p1: maxlimit=10 minlimit=3 mostfreqgap=10 toplayer_prefgap=4 toplayer_minwidth=5 toplayer_maxwidth=15 toplayer_prefwidth=5.2 midlayer1_minwidth=5 midlayer1_maxwidth=15 midlayer1_prefwidth=15 midlayer2_minwidth=5 midlayer2_maxwidth=15 midlayer2_prefwidth=15 midlayer3_minwidth=5 midlayer3_maxwidth=15 midlayer3_prefwidth=15 midlayer4_minwidth=5 midlayer4_maxwidth=15 midlayer4_prefwidth=15 midlayer5_minwidth=5 midlayer5_maxwidth=15 midlayer5_prefwidth=15 midlayer6_minwidth=5 midlayer6_maxwidth=15 midlayer6_prefwidth=15 midlayer7_minwidth=5 midlayer7_maxwidth=15 midlayer7_prefwidth=15 midlayer8_minwidth=5 midlayer8_maxwidth=15 midlayer8_prefwidth=15 bottomlayer_prefgap=4 bottomlayer_minwidth=5 bottomlayer_maxwidth=15 bottomlayer_prefwidth=5.2 maxuncoupledlength=500
FabricationTestPointUsage TestPointUsage [All] p1: valid=2 allowmultiple=FALSE
FabricationTestpoint Testpoint [All] p1: side=3 testpointundercomponent=TRUE minsize=40 maxsize=100 preferedsize=60 minholesize=0 maxholesize=40 preferedholesize=32 testpointgrid=1 allowsidetop=TRUE allowsidebottom=TRUE usegrid=TRUE gridtolerance=0.01
FanoutControl Fanout_LCC [IsLCC] p1: bgadir=Out bgaviamode=Centered fanoutstyle=Auto fanoutdirection=Alternating viagrid=1 // Fanout_LCC (Default Rule)
FanoutControl Fanout_BGA [IsBGA] p2: bgadir=Out bgaviamode=Centered fanoutstyle=Auto fanoutdirection=Alternating viagrid=1 // Fanout_BGA (Default Rule)
FanoutControl Fanout_Default [All] p4: bgadir=Out bgaviamode=Centered fanoutstyle=Auto fanoutdirection=Alternating viagrid=1 // Fanout_Default (Default Rule)
FanoutControl Fanout_Small [(CompPinCount < 5)] p5: bgadir=Out bgaviamode=Centered fanoutstyle=Auto fanoutdirection=OutThenIn viagrid=1 // Fanout_Small (Default Rule)
HoleSize [All] p1: absolutevalues=TRUE maxlimit=2500 minlimit=5 maxpercent=80.000 minpercent=20.000
HoleToHoleClearance [All] p1: gap=8 allowstackedmicrovias=TRUE
MatchedLengths "Buffer Outputs" [InNetClass('CMOS_BUF_Out')] p1: tolerance=10 checknetsindiffpair=FALSE checkdiffpairvsdiffpair=TRUE checkxsignals=TRUE checkothers=TRUE
MinimumSolderMaskSliver MinimumSolderMaskSliver_Logo [InComponentClass('Logo') vs InComponentClass('Logo')] p1: minsoldermaskwidth=0.7
MinimumSolderMaskSliver [All] p2: minsoldermaskwidth=3
PlaneConnect [All] p1: planeconnectstyle=Relief reliefexpansion=10 reliefentries=4 reliefconductorwidth=10 reliefairgap=10
PolygonConnect Thermals_USB [IsPolygon vs HasFootprint('Hirose_UX60SC-MB-5S8')] p1: thpad.connectstyle=Relief thpad.reliefconductorwidth=15 thpad.reliefentries=4 thpad.polygonreliefangle="90 Angle" thpad.airgapwidth=10 smdpad.connectstyle=Direct smdpad.reliefconductorwidth=10 smdpad.reliefentries=4 smdpad.polygonreliefangle="90 Angle" smdpad.airgapwidth=10 via.connectstyle=Direct via.reliefconductorwidth=10 via.reliefentries=4 via.polygonreliefangle="90 Angle" via.airgapwidth=10
PolygonConnect Thermals [IsPolygon vs (IsPad and HoleSize <= 41) or HasFootprint('500ASSP1M2QE')] p2: connectstyle=Direct reliefconductorwidth=10 reliefentries=4 polygonreliefangle="90 Angle" airgapwidth=10
PolygonConnect [All] p3: thpad.connectstyle=Relief thpad.reliefconductorwidth=20 thpad.reliefentries=4 thpad.polygonreliefangle="45 Angle" thpad.airgapwidth=10 smdpad.connectstyle=Direct smdpad.reliefconductorwidth=10 smdpad.reliefentries=4 smdpad.polygonreliefangle="90 Angle" smdpad.airgapwidth=10 via.connectstyle=Direct via.reliefconductorwidth=10 via.reliefentries=4 via.polygonreliefangle="90 Angle" via.airgapwidth=10
RoutingVias [All] p1: holewidth=28 width=50 viastyle="Through Hole" minholewidth=28 minwidth=50 maxholewidth=28 maxwidth=50
SMDEntry [All] p1: side=TRUE corner=TRUE anyangle=FALSE
SMDToCorner [All] p1: distance=0
SilkToBoardRegionClearance [Not ((IsComment or IsDesignator) And (Hide <> 'False')) and not InRegion(1000,500,4000,800)] p1:
SilkToSilkClearance [All] p1 off: silktosilkclearance=0.1
SilkToSolderMaskClearance SilkToComponentPadClearance [(IsPad or IsFill or IsRegion) and InAnycomponent] p1: minsilkscreentomaskgap=3 clearancetoexposedcopper=TRUE
SilkToSolderMaskClearance "Silk to Solder Mask Opening" [All] p2: minsilkscreentomaskgap=0 clearancetoexposedcopper=FALSE
SolderMaskExpansion [All] p1: expansion=1.97 istentingtop=FALSE
SupplyNets "Schematic Supply Nets_14" [InNet('1p8V_LVLSHIFT')] p1: voltage=0.000
SupplyNets "Schematic Supply Nets_13" [InNet('1p8V_BUFVCC')] p2: voltage=0.000
SupplyNets "Schematic Supply Nets_12" [InNet('VCM')] p3: voltage=0.000
SupplyNets "Schematic Supply Nets_11" [InNet('3p3V_EEPROM')] p4: voltage=0.000
SupplyNets "Schematic Supply Nets_10" [InNet('3p3V_AUX')] p5: voltage=0.000
SupplyNets "Schematic Supply Nets_9" [InNet('12V_FMC')] p6: voltage=0.000
SupplyNets "Schematic Supply Nets_8" [InNet('GND')] p7: voltage=0.000
SupplyNets "Schematic Supply Nets_7" [InNet('VADJ')] p8: voltage=0.000
SupplyNets "Schematic Supply Nets_6" [InNet('1p8V_AVDD')] p9: voltage=0.000
SupplyNets "Schematic Supply Nets_5" [InNet('1p8V_IOVDD')] p10: voltage=0.000
SupplyNets "Schematic Supply Nets_4" [InNet('2p3V')] p11: voltage=0.000
SupplyNets "Schematic Supply Nets_3" [InNet('USB_5V')] p12: voltage=0.000
SupplyNets "Schematic Supply Nets_2" [InNet('12V')] p13: voltage=0.000
SupplyNets "Schematic Supply Nets_1" [InNet('VREF')] p14: voltage=0.000
SupplyNets "Schematic Supply Nets" [InNet('3p3V_Utility')] p15: voltage=0.000
UnRoutedNet [All] p1: checkbadconnections=TRUE
Width [All] p1: maxlimit=100 minlimit=5 preferedwidth=5 toplayer_prefwidth=9.7 bottomlayer_prefwidth=9.7 minimp=50.000000 maximp=50.000000 favimp=50.000000
13 further rules are at their usual default settings.

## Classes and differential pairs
component class Shunt: SH-J12 SH-J13
net class CMOS_BUF_Out: DA0 DA1/FCLK DA2 DA3 DA4 DA5 DA6 DB0 DB1 DB2 DB3 DB4 DB5 DB6 DCLK
component class "Ouptut Buffer": C89 C90 C91 C92 R151 R152 R153 R154 R155 R156 R157 R158 R159 R160 R161 R162 R163 R164 R165 R166 R167 R168 R169 R170 R171 R172 R173 R174 R175 R176 R177 R178 R179 R180 R181 R182 U22
net class DiffPairIN: AIN_N AIN_P BIN_N BIN_P CLK_N CLK_P
net class DUTPwr: 1p8V_AVDD 1p8V_IOVDD
net class Power: 1p8V_AVDD 1p8V_BUFVCC 1p8V_IOVDD 1p8V_LVLSHIFT 2p3V 3p3V_Utility 12V VADJ
net class GenPwr: 1p8V_BUFVCC 1p8V_LVLSHIFT 2p3V 3p3V_Utility 12V
net class FMCPwr: VADJ
component class "CLK and DCLKIN": C48 C49 C50 C51 C52 C53 C54 C55 C56 J4 J5 J6 R63 R64 R65 R66 R67 R68 R69 R70 R71 R72 R73 SW3 T1 U17
component class "ADC Inputs": C57 C58 C59 C60 C61 C62 C63 C64 C65 C66 C67 C68 C69 C70 C71 C72 J7 J8 J9 J10 L1 L2 L3 L4 R74 R75 R76 R77 R78 R79 R80 R81 R82 R83 R84 R85 R86 R87 R88 R89 R90 R91 R92 R93 R94 R95 R96 R97 T2 T3
component class "Power DC-DC": C9 C10 C11 C12 C13 C14 C15 C16 FB1 PP2 R9 R10 R11 R12 R13 R14 U4
component class "Power LDO": C17 C18 C19 C20 C21 C22 C23 C24 C25 C26 C27 C28 C93 D4 D5 FB2 FB3 FC1 PP3 PP4 Q2 Q3 R15 R16 R17 R18 R19 R20 R21 R22 R23 R24 R25 R26 R27 R28 R29 R30 R31 U5 U6 U7 U8
component class "Power Sense ADC": C29 R32 R33 U9
component class "DUT IO": C73 C74 C75 C76 C77 C78 C79 C80 C81 C82 C83 C84 C85 C86 C87 J11 J12 J13 PP10 R98 R99 R100 R101 R102 R103 R104 R105 R106 R107 R108 R109 R110 R111 R112 R113 R114 R115 R116 R117 R118 R119 R120 R121 R122 R123 R124 R125 R126 R127 R128 R129 R130 R131 R132 R133 SH-J12 SH-J13 SW4 SW5 TP3 U1 U18 U19 U20
component class "Comms LVL Shift and MUX": C44 C45 C46 C47 PP5 PP6 PP7 PP8 PP9 R51 R52 R53 R54 R55 R56 R57 R58 R59 R60 R61 R62 R147 R148 R149 SW2 U13 U14 U15 U16 U23
component class "FMC+ Sections F-H, J, K": R141 R142 R143 R144 R146 R150
component class "USB Control FTDI": C30 C31 C32 C33 C34 C35 C36 C37 C38 C39 C40 C41 C42 C43 D6 FB4 FB5 J3 R34 R35 R36 R37 R38 R39 R40 R41 R42 R43 R44 R45 R46 R47 R48 R49 R50 U10 U11 U12 Y1
component class "12V Input, Efuse and 3p3V Utility": C1 C2 C3 C4 C5 C6 C7 C8 D1 D2 D3 F1 J2 PP1 Q1 R1 R2 R3 R4 R5 R6 R7 R8 SW1 TP1 TP2 U2 U3
component class "FMC+ Sections A-E": C88 J1 R134 R135 R136 R137 R138 R139 R140 R145 U21
component class "Hardware & Mechanicals": !PCB? FID1 FID2 FID3 H1 H3 LBL1 Logo1 Logo2 Logo3 Logo4 LOGO5 Logo6 ZZ1
differential pair SMA_CLK: +SMA_CLK_P -SMA_CLK_N
differential pair CLK: +CLK_P -CLK_N
differential pair BIN: +BIN_P -BIN_N
differential pair AIN: +AIN_P -AIN_N

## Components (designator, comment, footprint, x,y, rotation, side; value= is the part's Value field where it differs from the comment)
C1 "C2012X7R1H105K125AB" 0805L_cap 832.9,516.43 r90 bottom value="1 uF"
C2 "C2012X7R1H105K125AB" 0805L_cap 1233.56,533.64 r180 bottom value="1 uF"
C3 "C2012X7R1H105K125AB" 0805L_cap 1233.56,463.64 r180 bottom value="1 uF"
C4 "CGA3E2X7R1H102K080AA" 0603L_cap 1304.09,248.4 r180 bottom value="0.001 uF"
C5 "CGA3E2X7R1H102K080AA" 0603L_cap 1322.87,298.4 r180 bottom value="0.001 uF"
C6 "C2012X7S1E106K125AC" 0805L_cap 1198.13,628.89 r270 bottom value="10 uF"
C7 "C2012X7S1A226M125AC" 0805L_cap 952.5,621.47 r90 bottom value="22 uF"
C8 "CGA2B2X7R1H332K050BA" 0402L_cap#1 1133.88,704.14 r90 bottom value="3300 pF"
C9 "C2012X7S1E106K125AC" 0805L_cap 392.26,964.72 r270 bottom value="10 uF"
C10 "C2012X7S1E106K125AC" 0805L_cap 322.26,964.72 r270 bottom value="10 uF"
C11 "C2012X7S1A226M125AC" 0805L_cap 156.79,1155 r0 bottom value="22 uF"
C12 "C2012X7S1A226M125AC" 0805L_cap 156.79,1225.06 r0 bottom value="22 uF"
C13 "C2012X7S1A226M125AC" 0805L_cap 280.8,1155 r180 bottom value="22 uF"
C14 "C2012X7S1A226M125AC" 0805L_cap 220.8,1338.49 r0 bottom value="22 uF"
C15 "C2012X7S1A226M125AC" 0805L_cap 344.81,1338.49 r180 bottom value="22 uF"
C16 "CGA2B1X5R1C224M050BC" 0402L_cap#1 217.89,816.44 r270 bottom value="0.22 uF"
C17 "GRT155R71E104KE01J" 0402L_cap#1 941.14,1550.75 r0 top value="0.1 uF"
C18 "C2012X7S1E106K125AC" 0805L_cap 480.98,1598.19 r270 top value="10 uF"
C19 "GRT155R71E104KE01J" 0402L_cap#1 536.41,1578.51 r270 top value="0.1 uF"
C20 "C2012X7S1E106K125AC" 0805L_cap 793.72,1575.5 r270 top value="10 uF"
C21 "GRM188R60J476ME15D" 0603L_cap 768.74,1755.8 r270 top value="47 uF"
C22 "C1005X5R1E105K050BC" 0402L_cap#2 712.72,1485.59 r90 top value="1 uF"
C23 "GRT155R71E104KE01J" 0402L_cap#1 941.14,1150.75 r0 top value="0.1 uF"
C24 "C2012X7S1E106K125AC" 0805L_cap 480.98,1198.19 r270 top value="10 uF"
C25 "GRT155R71E104KE01J" 0402L_cap#1 536.41,1178.5 r270 top value="0.1 uF"
C26 "C2012X7S1E106K125AC" 0805L_cap 793.72,1175.5 r270 top value="10 uF"
C27 "GRM188R60J476ME15D" 0603L_cap 768.74,1355.8 r270 top value="47 uF"
C28 "C1005X5R1E105K050BC" 0402L_cap#2 712.72,1085.59 r90 top value="1 uF"
C29 "GRT155R71E104KE01J" 0402L_cap#1 1154.09,1948.29 r0 bottom value="0.1 uF"
C30 "GRT155R71E104KE01J" 0402L_cap#1 670.29,2168.6 r270 bottom value="0.1 uF"
C31 "C1005X5R1A475K050BC" 0402L_cap#1 377.37,2160.56 r90 top value="4.7 uF"
C32 "GRT155R71E104KE01J" 0402L_cap#1 411.37,2160.56 r90 top value="0.1 uF"
C33 "C1005X5R1A475K050BC" 0402L_cap#1 376,2326.08 r270 top value="4.7 uF"
C34 "GRT155R71E104KE01J" 0402L_cap#1 410,2326.08 r270 top value="0.1 uF"
C35 "CGA3E1X5R1A335K080AC" 0603L_cap 846.42,2148.91 r0 bottom value="3.3 uF"
C36 "GRT155R71E104KE01J" 0402L_cap#1 847.98,2267.02 r270 bottom value="0.1 uF"
C37 "GRT155R71E104KE01J" 0402L_cap#1 509.93,2109.54 r0 bottom value="0.1 uF"
C38 "GRT155R71E104KE01J" 0402L_cap#1 620.59,2048.32 r180 bottom value="0.1 uF"
C39 "GRT155R71E104KE01J" 0402L_cap#1 699.33,2511.98 r270 bottom value="0.1 uF"
C40 "GRT155R71E104KE01J" 0402L_cap#1 837.13,2033.32 r180 bottom value="0.1 uF"
C41 "GRT155R71E104KE01J" 0402L_cap#1 817.44,2362.61 r90 bottom value="0.1 uF"
C42 "GJM0336C1E180JB01J" 0201_cap 313.91,2417.36 r135 top value="18 pF"
C43 "GJM0336C1E180JB01J" 0201_cap 508.05,2611.5 r135 top value="18 pF"
C44 "GRT155R71E104KE01J" 0402L_cap#1 1242.17,2323.6 r0 top value="0.1 uF"
C45 "GRT155R71E104KE01J" 0402L_cap#1 1008.98,2088.62 r90 top value="0.1 uF"
C46 "GRT155R71E104KE01J" 0402L_cap#1 1099.53,2088.62 r90 top value="0.1 uF"
C47 "GRT155R71E104KE01J" 0402L_cap#1 1229.33,2165.39 r0 top value="0.1 uF"
C48 "GRM033Z71C104ME14D" 0201_cap 1967.18,1244.35 r0 top value="0.1 uF"
C49 "GRM033Z71C104ME14D" 0201_cap 1872.13,1266.57 r0 top value="0.1 uF"
C50 "GRM033Z71C104ME14D" 0201_cap 1495.08,1233.05 r180 top value="0.1 uF"
C51 "GRM033Z71C104ME14D" 0201_cap 1877.08,1233.05 r0 top value="0.1 uF"
C52 "GRM033Z71C104ME14D" 0201_cap 1461.11,969.07 r270 top value="0.1 uF"
C53 "GRM033Z71C104ME14D" 0201_cap 1872.13,1199.53 r180 top value="0.1 uF"
C54 "GRM033Z71C104ME14D" 0201_cap 1967.18,1221.75 r0 top value="0.1 uF"
C55 "GRT155R71E104KE01J" 0402L_cap#1 2633.64,759.68 r90 top value="0.1 uF"
C56 "GRM033Z71C104ME14D" 0201_cap 2771.24,825.27 r0 top value="0.1 uF"
C57 "GRM033Z71C104ME14D" 0201_cap 1863.45,409.74 r90 top value="0.1 uF"
C58 "GRM033Z71C104ME14D" 0201_cap 1874.47,398.72 r0 top value="0.1 uF"
C59 "GRM033Z71C104ME14D" 0201_cap 2104.93,809.74 r90 top value="0.1 uF"
C60 "GRM033Z71C104ME14D" 0201_cap 2138.45,804.74 r90 top value="0.1 uF"
C61 "GRM033Z71C104ME14D" 0201_cap 2138.45,983.24 r90 top value="0.1 uF"
C62 "CGA1A2X7R1E101M030BA" 0201_cap 2138.95,885.81 r180 top value="100 pF"
C63 "GRM033Z71C104ME14D" 0201_cap 2172.95,809.74 r270 top value="0.1 uF"
C64 "GRM033Z71C104ME14D" 0201_cap 2413.45,409.74 r90 top value="0.1 uF"
C65 "GRM033Z71C104ME14D" 0201_cap 2412.46,2087.85 r270 top value="0.1 uF"
C66 "GRM033Z71C104ME14D" 0201_cap 2401.44,2098.88 r180 top value="0.1 uF"
C67 "GRM033Z71C104ME14D" 0201_cap 2171.97,1687.85 r270 top value="0.1 uF"
C68 "GRM033Z71C104ME14D" 0201_cap 2138.45,1512.97 r270 top value="0.1 uF"
C69 "GRM033Z71C104ME14D" 0201_cap 2137.46,1692.85 r270 top value="0.1 uF"
C70 "CGA1A2X7R1E101M030BA" 0201_cap 2137.94,1611.78 r0 top value="100 pF"
C71 "GRM033Z71C104ME14D" 0201_cap 2104.93,1687.85 r90 top value="0.1 uF"
C72 "GRM033Z71C104ME14D" 0201_cap 1862.46,2087.85 r270 top value="0.1 uF"
C73 "GRM033R61A105ME44D" 0201_cap 2177.82,1155.91 r270 bottom value="1 uF"
C74 "GRM033Z71C104ME14D" 0201_cap 2093.51,1256.67 r180 bottom value="0.1 uF"
C75 "GRM033Z71C104ME14D" 0201_cap 2170,1380 r270 bottom value="0.1 uF"
C76 "GRM033R61A105ME44D" 0201_cap 2287.97,1165.14 r135 bottom value="1 uF"
C77 "GRM033Z71C104ME14D" 0201_cap 2287.97,1332.46 r225 bottom value="0.1 uF"
C78 "GRM033R61A105ME44D" 0201_cap 2049.75,1210.43 r0 bottom value="1 uF"
C79 "GRM033Z71C104ME14D" 0201_cap 2093.51,1210.43 r180 bottom value="0.1 uF"
C80 "GRT155R71E104KE01J" 0402L_cap#1 1563.61,691.02 r90 bottom value="0.1 uF"
C81 "GRT155R71E104KE01J" 0402L_cap#1 1506.58,483.65 r0 bottom value="0.1 uF"
C82 "0402ZD106MAT2A" 0402L_cap#1 2090.89,1298.92 r180 bottom value="10 uF"
C83 "GRM033Z71C104ME14D" 0201_cap 2082.23,1326.92 r180 bottom value="0.1 uF"
C84 "GRM033Z71C104ME14D" 0201_cap 2051.18,1298.92 r0 top value="0.1 uF"
C85 "GRT155R71E104KE01J" 0402L_cap#1 2032.8,1500.86 r135 bottom value="0.1 uF"
C86 "0402ZD106MAT2A" 0402L_cap#1 2021.52,1272.42 r0 bottom value="10 uF"
C87 "GRM033Z71C104ME14D" 0201_cap 2025.18,1248.42 r0 bottom value="0.1 uF"
C88 "GRT155R71E104KE01J" 0402L_cap#1 3221.49,194.99 r180 top value="0.1 uF"
C89 "GRT155R71E104KE01J" 0402L_cap#1 2575,1337.38 r90 top value="0.1 uF"
C90 "GRT155R71E104KE01J" 0402L_cap#1 2940.28,1337.38 r90 top value="0.1 uF"
C91 "GRT155R71E104KE01J" 0402L_cap#1 2945.28,1120.84 r90 top value="0.1 uF"
C92 "GRT155R71E104KE01J" 0402L_cap#1 2570,1120.84 r90 top value="0.1 uF"
C93 "GRM188R61E106KA73J" 0603L_cap 966.48,1035.99 r90 bottom value="10 uF"
D1 "LTST-C191TGKT" LED_LTST-C190-Green 325.14,119.85 r0 top
D2 "SMBJ15CA" SMBJ15CA 961.01,303.18 r90 bottom
D3 "MBR130T1G" SOD-123 1061.77,539.36 r180 bottom
D4 "LTST-C191TGKT" LED_LTST-C190-Green 1065,2633.58 r270 top
D5 "LTST-C191TGKT" LED_LTST-C190-Green 1160,2633.58 r270 top
D6 "LTST-C191TGKT" LED_LTST-C190-Green 310,2050 r0 top
F1 "BNX002-11" FIL_BNX002-11 734.47,319.58 r90 top
FB1 "BLE18PS080SN1D" 0603L 255.58,1257.62 r90 bottom value=-
FB2 "BLM21SP471SN1D" 0805L 844.27,1716.43 r180 top value=-
FB3 "BLM21SP471SN1D" 0805L 844.27,1316.43 r180 top value=-
FB4 "NFZ15SG151SN11D" 0402L#1 341.37,2160.56 r90 top value=-
FB5 "NFZ15SG151SN11D" 0402L#1 340,2326.08 r270 top value=-
FC1 "dcp00001" NFM31PC 850.54,1061.05 r0 bottom value=27uF
FID1 "Fiducial Mark" Fiducial10-20 281.88,50 r90 top
FID2 "Fiducial Mark" Fiducial10-20 3720,110 r90 top
FID3 "Fiducial Mark" Fiducial10-20 3361.42,2598.27 r90 top
H1 "CBTS130A" cbts130a 130,2595 r0 top locked
H3 "CBTS130A" cbts130a 125,125 r0 top
J1 "ASP-134488-01" SAMTEC_ASP-134488-01 3586.42,1359.27 r90 bottom locked
J2 "RAPC722X" RAPC722X -148.41,443 r0 top
J3 "USB4105-GF-A" FP-USB4105-GF-A_CONN_USB_9MM58_7MM53-MFG 108.82,2257.18 r270 top
J4 "132134-15" FP-132134-15_CONN_SMA_JACK-MFG 1261.11,1508.05 r0 top
J5 "132134-15" FP-132134-15_CONN_SMA_JACK-MFG 1261.11,958.05 r0 top
J6 "132134-15" FP-132134-15_CONN_SMA_JACK-MFG 2882.27,625.27 r0 top
J7 "132134-15" FP-132134-15_CONN_SMA_JACK-MFG 1863.45,198.72 r0 top
J8 "132134-15" FP-132134-15_CONN_SMA_JACK-MFG 2413.45,198.72 r0 top
J9 "132134-15" FP-132134-15_CONN_SMA_JACK-MFG 2412.46,2298.88 r0 top
J10 "132134-15" FP-132134-15_CONN_SMA_JACK-MFG 1862.46,2298.88 r0 top
J11 "132134-15" FP-132134-15_CONN_SMA_JACK-MFG 2972.46,2238.88 r0 top
J12 "TSW-103-14-L-S" PBC03SAAN 2672.46,1888.88 r270 top
J13 "GRPB021VWVN-RC" HDR_2x1_TH_VT_50mil 2005.08,1425.37 r315 top
L1 "180 nH" IND_LQG15H 2104.93,927.51 r90 top
L2 "180 nH" IND_LQG15H 2171.97,927.51 r90 top
L3 "180 nH" IND_LQG15H 2171.97,1570.08 r270 top
L4 "180 nH" IND_LQG15H 2104.93,1570.08 r270 top
LBL1 "THT-14-423-10" Label_650x200 3740,1420 r270 top
Logo1 "FDL Logo" FDL_Small 3695,230 r0 top
Logo2 "FCC disclaimer" FCC_disclaimer 2695,2293.66 r90 bottom
Logo3 "ESD Overlay" ESD_Overlay_Small 2485,1055 r0 top
Logo4 "WEEE" WEEE_Minimum 1670,1990 r180 bottom
LOGO5 "CE Mark" CE_Mark_5mm 3123.58,2560 r180 bottom
Logo6 "Texas Instruments" TI_Stacked_Overlay_Small_Vertical 3473.23,1903.13 r270 top
PP1 "Probe Point" ProbePoint_TH_40mil 952.5,720.99 r180 top
PP2 "Probe Point" ProbePoint_TH_40mil 318.14,1245.07 r90 bottom
PP3 "Probe Point" ProbePoint_TH_40mil 824.74,1786.43 r180 top
PP4 "Probe Point" ProbePoint_TH_40mil 824.74,1386.43 r180 top
PP5 "Probe Point" ProbePoint_TH_40mil 1351.85,2284.23 r0 top
PP6 "Probe Point" ProbePoint_TH_40mil 1351.85,2362.97 r0 top
PP7 "Probe Point" ProbePoint_TH_40mil 1385,2125.97 r0 top
PP8 "Probe Point" ProbePoint_TH_40mil 1385,2245.97 r0 top
PP9 "Probe Point" ProbePoint_TH_40mil 1385,2185.97 r0 top
PP10 "Probe Point" ProbePoint_TH_40mil 1458.21,710.71 r180 top
Q1 "CSD15571Q2" DQK0006C 837.23,318.16 r270 bottom
Q2 "CSD13380F3" YJM0003A 1101.89,2653.11 r0 bottom
Q3 "CSD13380F3" YJM0003A 1196.89,2653.11 r0 bottom
R1 "ERA-2AED104X" 0402L#2 1216.76,258.4 r180 bottom value="100 kΩ"
R2 "ERJ-2RKF4532X" 0402L#2 1310.27,408.64 r180 bottom value="45.3 kΩ"
R3 "ERJ-HP6F1002V" 0805L 684.2,119.85 r180 bottom value="10 kΩ"
R4 "ERA-2AEB1622X" 0402L#2 1296.62,205.62 r180 bottom value="16.2 kΩ"
R5 "ERA-2AEB103X" 0402L#2 1069.29,779.51 r90 bottom value="10 kΩ"
R6 "ERA-2AEB103X" 0402L#2 1133.88,621.47 r270 bottom value="10 kΩ"
R7 "ERA-2AEB3742X" 0402L#2 1035.7,779.51 r90 bottom value="37.4 kΩ"
R8 "ERJ-2RKF1202X" 0402L#2 1002.1,779.51 r270 bottom value="12 kΩ"
R9 "ERJ-U020R00X" 0402L#2 1121.72,759.83 r180 bottom value="0 Ω"
R10 "ERA-2AEB103X" 0402L#2 251.89,816.44 r270 bottom value="10 kΩ"
R11 "ERJ-2RKF1002X" 0402L#2 81.89,816.44 r270 bottom value="10 kΩ"
R12 "ERA-2AEB9311X" 0402L#2 183.89,816.44 r270 bottom value="9.31 kΩ"
R13 "ERJ-2RKF8062X" 0402L#2 115.89,816.44 r90 bottom value="80.6 kΩ"
R14 "ERA-2AEB4871X" 0402L#2 149.89,816.44 r90 bottom value="4.87 kΩ"
R15 "ERA-2AEB103X" 0402L#2 522.48,1485.59 r270 top value="10 kΩ"
R16 "ERJ-2RKF1002X" 0402L#2 519.61,1532.05 r180 bottom value="10 kΩ"
R17 "WSLP0603R1000FEA" CCS0603FLxLxx 858.46,1590.51 r90 top value="100 mΩ"
R18 "ERJ-HP6F1002V" 0805L 1065,2544.53 r90 bottom value="10 kΩ"
R19 "RT0402BRD0788K7L" 0402L#2 709.12,1571.42 r270 top value="88.7 kΩ"
R20 "ERA-2AEB1242X" 0402L#2 742.72,1610.79 r270 top value="12.4 kΩ"
R21 "ERJ-2RKF1202X" 0402L#1 747.72,1485.59 r90 top value="12 kΩ"
R22 "ERJ-U020R00X" 0402L#2 801.4,1465.91 r180 top value="0 Ω"
R23 "ERJ-U020R00X" 0402L#2 341.79,836.12 r180 bottom value="0 Ω"
R24 "ERA-2AEB103X" 0402L#2 522.48,1085.59 r270 top value="10 kΩ"
R25 "ERJ-HP6F1002V" 0805L 1160,2544.53 r90 bottom value="10 kΩ"
R26 "ERJ-2RKF1002X" 0402L#2 519.61,1132.05 r180 bottom value="10 kΩ"
R27 "WSLP0603R1000FEA" CCS0603FLxLxx 858.46,1190.51 r90 top value="100 mΩ"
R28 "RT0402BRD0788K7L" 0402L#2 709.12,1171.42 r270 top value="88.7 kΩ"
R29 "ERA-2AEB1242X" 0402L#2 742.72,1210.79 r270 top value="12.4 kΩ"
R30 "ERJ-2RKF1202X" 0402L#1 747.72,1085.59 r90 top value="12 kΩ"
R31 "ERJ-U020R00X" 0402L#2 801.4,1065.91 r180 top value="0 Ω"
R32 "ERA-2AEB103X" 0402L#2 1204.09,2027.82 r180 bottom value="10 kΩ"
R33 "ERA-2AEB103X" 0402L#2 1353.7,2027.82 r0 bottom value="10 kΩ"
R34 "ERA-2AEB103X" 0402L#2 699.33,2106.22 r180 bottom value="10 kΩ"
R35 "ERJ-2RKF4701X" 0402L#2 738.7,2321.95 r270 bottom value="4.7 kΩ"
R36 "ERJ-1GN0R00C" 0201 403.98,2070.17 r180 top value="0 Ω"
R37 "ERA-2AEB103X" 0402L#2 699.33,2321.95 r90 bottom value="10 kΩ"
R38 "ERJ-2RKF4701X" 0402L#2 807.6,2060.88 r180 bottom value="4.7 kΩ"
R39 "ERJ-1GN0R00C" 0201 719.02,2075.19 r90 bottom value="0 Ω"
R40 "ERJ-2RKF1000X" 0402L#2 758.39,2080.57 r270 bottom value="100 Ω"
R41 "ERJ-2GEJ100X" 0402L#2 390.32,2109.22 r180 top value="10 Ω"
R42 "ERJ-6GEY0R00V" 0805L 189.11,2024.59 r0 bottom value="0 Ω"
R43 "ERJ-2GEJ100X" 0402L#2 349.84,2254.74 r0 top value="10 Ω"
R44 "ERJ-2GEJ100X" 0402L#2 349.84,2220.25 r0 top value="10 Ω"
R45 "ERJ-2GEJ222X" 0402L#2 340,2030.31 r90 bottom value="2.2 kΩ"
R46 "ERJ-2RKF1202X" 0402L#2 512,2238.3 r90 bottom value="12 kΩ"
R47 "ERA-2AEB103X" 0402L#2 596.22,2506.98 r90 bottom value="10 kΩ"
R48 "ERA-2AEB103X" 0402L#2 689.97,2387.5 r0 bottom value="10 kΩ"
R49 "ERA-2AEB103X" 0402L#2 561.54,2506.98 r90 bottom value="10 kΩ"
R50 "ERJ-2GEJ222X" 0402L#2 625.6,2387.5 r180 bottom value="2.2 kΩ"
R51 "ERA-2AEB103X" 0402L#2 187.16,1915 r0 bottom value="10 kΩ"
R52 "ERA-2AEB103X" 0402L#2 392.95,2025.63 r90 bottom value="10 kΩ"
R53 "ERA-2AEB103X" 0402L#2 541.85,1978.01 r90 bottom value="10 kΩ"
R54 "ERA-2AEB103X" 0402L#2 581.22,1978.01 r90 bottom value="10 kΩ"
R55 "ERA-2AEB103X" 0402L#2 1094.84,2192.04 r0 top value="10 kΩ"
R56 "ERA-2AEB103X" 0402L#2 1309.41,2247.34 r180 bottom value="10 kΩ"
R57 "ERJ-2RKF1000X" 0402L#2 1337.95,2179.32 r90 bottom value="100 Ω"
R58 "ERA-2AEB103X" 0402L#2 1119.97,2243.02 r180 bottom value="10 kΩ"
R59 "ERA-2AEB103X" 0402L#2 1444.21,2305.47 r90 bottom value="10 kΩ"
R60 "ERA-2AEB103X" 0402L#2 1478.89,2300.47 r90 bottom value="10 kΩ"
R61 "ERA-2AEB103X" 0402L#2 1412.13,2318.95 r90 bottom value="10 kΩ"
R62 "ERA-2AEB103X" 0402L#2 1054.6,2290.74 r0 bottom value="10 kΩ"
R63 "ERJ-1GN0R00C" 0201 1883.16,1277.59 r270 top value="0 Ω"
R64 "ERJ-1GN0R00C" 0201 1472.13,1508.05 r0 top value="0 Ω"
R65 "ERJ-1GNF49R9C" 0201 1922.13,1244.35 r0 top value="49.9 Ω"
R66 "ERJ-1GNF1001C" 0201 2001.2,1233.32 r90 top value="1 kΩ"
R67 "ERJ-1GNF49R9C" 0201 1922.13,1221.75 r180 top value="49.9 Ω"
R68 "ERJ-1GN0R00C" 0201 1472.13,958.05 r0 top value="0 Ω"
R69 "ERJ-1GN0R00C" 0201 1883.16,1188.5 r90 top value="0 Ω"
R70 "ERJ-1GNF1001C" 0201 2690.22,814.24 r270 top value="1 kΩ"
R71 "ERJ-1GNF49R9C" 0201 2893.29,795.27 r180 top value="49.9 Ω"
R72 "ERJ-1GNF1001C" 0201 2720.22,836.29 r270 top value="1 kΩ"
R73 "ERA-2AEB103X" 0402L#2 3023.45,79.03 r270 bottom value="10 kΩ"
R74 "ERJ-1GN0R00C" 0201 2093.9,820.77 r0 top value="0 Ω"
R75 "ERJ-1GN0R00C" 0201 2104.93,854.79 r90 top value="0 Ω"
R76 "ERJ-1GNF33R0C" 0201 2076.93,983.24 r90 top value="33 Ω"
R77 "ERJ-1GNF10R0C" 0201 2127.15,1053.29 r90 top value="10 Ω"
R78 "ERJ-1GN0R00C" 0201 2104.93,983.24 r90 top value="0 Ω"
R79 "ERJ-1GNF24R9C" 0201 2115.95,1017.26 r180 top value="24.9 Ω"
R80 "ERJ-1GNF24R9C" 0201 2160.94,1017.26 r180 top value="24.9 Ω"
R81 "ERJ-1GN0R00C" 0201 2171.97,983.24 r90 top value="0 Ω"
R82 "ERJ-1GN0R00C" 0201 2183.98,820.77 r180 top value="0 Ω"
R83 "ERJ-1GN0R00C" 0201 2172.95,854.79 r90 top value="0 Ω"
R84 "ERJ-1GNF33R0C" 0201 2199.97,983.24 r90 top value="33 Ω"
R85 "ERJ-1GNF10R0C" 0201 2149.75,1053.29 r90 top value="10 Ω"
R86 "ERJ-1GN0R00C" 0201 2182.99,1676.83 r180 top value="0 Ω"
R87 "ERJ-1GN0R00C" 0201 2171.97,1642.8 r270 top value="0 Ω"
R88 "ERJ-1GNF33R0C" 0201 2199.97,1514.36 r270 top value="33 Ω"
R89 "ERJ-1GNF10R0C" 0201 2149.75,1444.31 r270 top value="10 Ω"
R90 "ERJ-1GN0R00C" 0201 2171.97,1514.36 r270 top value="0 Ω"
R91 "ERJ-1GNF24R9C" 0201 2160.94,1478.94 r0 top value="24.9 Ω"
R92 "ERJ-1GNF24R9C" 0201 2115.95,1478.94 r0 top value="24.9 Ω"
R93 "ERJ-1GN0R00C" 0201 2104.93,1514.36 r270 top value="0 Ω"
R94 "ERJ-1GN0R00C" 0201 2093.9,1676.83 r0 top value="0 Ω"
R95 "ERJ-1GN0R00C" 0201 2104.93,1642.8 r270 top value="0 Ω"
R96 "ERJ-1GNF33R0C" 0201 2076.93,1514.36 r270 top value="33 Ω"
R97 "ERJ-1GNF10R0C" 0201 2127.15,1444.31 r270 top value="10 Ω"
R98 "ERJ-1GN0R00C" 0201 2326.2,1248.8 r0 top value="0 Ω"
R99 "ERJ-1GN0R00C" 0201 2216.66,1103.29 r270 top value="0 Ω"
R100 "ERJ-1GN0R00C" 0201 2239.76,1103.29 r270 top value="0 Ω"
R101 "ERA-2AEB103X" 0402L#2 2612.93,1908.56 r270 bottom value="10 kΩ"
R102 "ERJ-1GN0R00C" 0201 2262.86,1103.29 r270 top value="0 Ω"
R103 "ERJ-1GN0R00C" 0201 2285.96,1103.29 r270 top value="0 Ω"
R104 "ERJ-1GN0R00C" 0201 2326.2,1179.5 r0 top value="0 Ω"
R105 "ERJ-1GN0R00C" 0201 2326.2,1202.6 r0 top value="0 Ω"
R106 "ERJ-1GN0R00C" 0201 2326.2,1225.7 r0 top value="0 Ω"
R107 "ERJ-6GEY0R00V" 0805L 2960,1715 r180 top value="0 Ω"
R108 "ERJ-6GEY0R00V" 0805L 2959.53,1645 r180 top value="0 Ω"
R109 "ERJ-6GEY0R00V" 0805L 2960.75,1577.11 r180 top value="0 Ω"
R110 "ERA-2AEB103X" 0402L#2 2722.46,2008.56 r90 bottom value="10 kΩ"
R111 "ERJ-1GN0R00C" 0201 2216.66,1394.31 r90 top value="0 Ω"
R112 "ERJ-1GN0R00C" 0201 2239.76,1394.31 r90 top value="0 Ω"
R113 "ERJ-1GN0R00C" 0201 2262.86,1394.31 r90 top value="0 Ω"
R114 "ERJ-1GN0R00C" 0201 2285.96,1394.31 r90 top value="0 Ω"
R115 "ERJ-1GN0R00C" 0201 2326.2,1318.1 r0 top value="0 Ω"
R116 "ERJ-1GN0R00C" 0201 2326.2,1295 r0 top value="0 Ω"
R117 "ERJ-1GN0R00C" 0201 2326.2,1271.9 r0 top value="0 Ω"
R118 "ERJ-1GN0R00C" 0201 2030.18,1319.66 r0 bottom value="0 Ω"
R119 "ERJ-1GN0R00C" 0201 2021.2,1125.91 r90 bottom value="0 Ω"
R120 "ERJ-2GEJ104X" 0402L#2 1496.21,691.02 r270 bottom value="100 kΩ"
R121 "ERJ-U020R00X" 0402L#2 1526.21,691.02 r270 bottom value="0 Ω"
R122 "ERA-2AEB103X" 0402L#2 1586.78,334.78 r180 bottom value="10 kΩ"
R123 "ERJ-1GN0R00C" 0201 2358.25,1441.5 r180 top value="0 Ω"
R124 "ERJ-2GEJ104X" 0402L#2 1638.41,691.02 r90 bottom value="100 kΩ"
R125 "ERJ-1GN0R00C" 0201 2193.56,1394.31 r270 top value="0 Ω"
R126 "ERJ-1GN0R00C" 0201 2071.2,1155.91 r90 bottom value="0 Ω"
R127 "ERJ-1GN0R00C" 0201 2347.23,1430.48 r90 top value="0 Ω"
R128 "ERJ-U020R00X" 0402L#2 1601.01,691.02 r270 bottom value="0 Ω"
R129 "ERJ-1GN0R00C" 0201 2193.56,1103.29 r90 top value="0 Ω"
R130 "ERJ-1GNF2491C" 0201 1691.92,1705.73 r315 bottom value="2.49 kΩ"
R131 "ERJ-1GN0R00C" 0201 1878.7,1654.95 r135 bottom value="0 Ω"
R132 "ERJ-1GNF3001C" 0201 2083.75,1374.15 r180 bottom value="3 kΩ"
R133 "ERJ-1GNF4991C" 0201 1727.28,1741.09 r135 bottom value="4.99 kΩ"
R134 "ERJ-1GNJ103C" 0201 3365.08,219.99 r180 top value="10 kΩ"
R135 "ERJ-1GNJ103C" 0201 3365.08,244.68 r180 top value="10 kΩ"
R136 "ERJ-1GNJ103C" 0201 3365.08,269.36 r180 top value="10 kΩ"
R137 "ERJ-1GN0R00C" 0201 3611.42,2360 r0 top value="0 Ω"
R138 "ERJ-1GN0R00C" 0201 3661.42,858.96 r90 top value="0 Ω"
R139 "ERJ-1GN0R00C" 0201 3702.65,874.5 r45 top value="0 Ω"
R140 "ERJ-1GN0R00C" 0201 3702.65,824.5 r45 top value="0 Ω"
R141 "ERJ-1GN0R00C" 0201 3325.39,1308.27 r0 top value="0 Ω"
R142 "ERJ-1GN0R00C" 0201 3523.92,970.77 r135 top value="0 Ω"
R143 "ERJ-1GN0R00C" 0201 3523.92,870.77 r135 top value="0 Ω"
R144 "ERJ-1GN0R00C" 0201 3523.92,820.77 r135 top value="0 Ω"
R145 "ERJ-1GNF2200C" 0201 3737.11,383.27 r0 top value="220 Ω"
R146 "ERJ-1GN0R00C" 0201 3523.92,720.77 r135 top value="0 Ω"
R147 "ERA-2AEB103X" 0402L#2 1133.18,2419.8 r90 bottom value="10 kΩ"
R148 "ERA-2AEB103X" 0402L#2 1015.23,2290.74 r0 bottom value="10 kΩ"
R149 "ERJ-2RKF1000X" 0402L#2 1034.92,2345.43 r270 bottom value="100 Ω"
R150 "ERJ-2RKF1000X" 0402L#2 3461.42,2258.27 r90 top value="100 Ω"
R151 "ERJ-1GNJ123C" 0201 2656.02,1510.29 r0 top value="12 kΩ"
R152 "ERJ-1GN0R00C" 0201 2609.74,1133.69 r0 top value="0 Ω"
R153 "ERJ-1GN0R00C" 0201 2882.97,1133.69 r0 top value="0 Ω"
R154 "ERJ-1GN0R00C" 0201 2632.31,1111 r0 top value="0 Ω"
R155 "ERJ-1GN0R00C" 0201 2905.53,1111 r0 top value="0 Ω"
R156 "ERJ-1GN0R00C" 0201 2609.74,1074.63 r0 top value="0 Ω"
R157 "ERJ-1GN0R00C" 0201 2882.97,1074.63 r0 top value="0 Ω"
R158 "ERJ-1GN0R00C" 0201 2632.31,1051.95 r0 top value="0 Ω"
R159 "ERJ-1GN0R00C" 0201 2905.53,1051.95 r0 top value="0 Ω"
R160 "ERJ-1GN0R00C" 0201 2632.31,1170.06 r0 top value="0 Ω"
R161 "ERJ-1GN0R00C" 0201 2905.53,1170.06 r0 top value="0 Ω"
R162 "ERJ-1GN0R00C" 0201 2609.74,1192.74 r0 top value="0 Ω"
R163 "ERJ-1GN0R00C" 0201 2882.97,1192.74 r0 top value="0 Ω"
R164 "ERJ-1GN0R00C" 0201 2632.31,1226.11 r0 top value="0 Ω"
R165 "ERJ-1GN0R00C" 0201 2882.97,1226.11 r0 top value="0 Ω"
R166 "ERJ-1GN0R00C" 0201 2609.74,1248.8 r0 top value="0 Ω"
R167 "ERJ-1GN0R00C" 0201 2905.53,1248.8 r0 top value="0 Ω"
R168 "ERJ-1GN0R00C" 0201 2609.74,1468.33 r0 top value="0 Ω"
R169 "ERJ-1GN0R00C" 0201 2883.04,1465.33 r0 top value="0 Ω"
R170 "ERJ-1GN0R00C" 0201 2632.31,1445.65 r0 top value="0 Ω"
R171 "ERJ-1GN0R00C" 0201 2905.6,1442.65 r0 top value="0 Ω"
R172 "ERJ-1GN0R00C" 0201 2609.74,1409.28 r0 top value="0 Ω"
R173 "ERJ-1GN0R00C" 0201 2882.97,1406.28 r0 top value="0 Ω"
R174 "ERJ-1GN0R00C" 0201 2632.31,1386.59 r0 top value="0 Ω"
R175 "ERJ-1GN0R00C" 0201 2905.53,1383.59 r0 top value="0 Ω"
R176 "ERJ-1GN0R00C" 0201 2632.31,1327.54 r0 top value="0 Ω"
R177 "ERJ-1GN0R00C" 0201 2882.97,1327.54 r0 top value="0 Ω"
R178 "ERJ-1GN0R00C" 0201 2609.74,1294.17 r0 top value="0 Ω"
R179 "ERJ-1GN0R00C" 0201 2905.53,1294.17 r0 top value="0 Ω"
R180 "ERJ-1GN0R00C" 0201 2632.31,1271.48 r0 top value="0 Ω"
R181 "ERJ-1GN0R00C" 0201 2882.97,1271.48 r0 top value="0 Ω"
R182 "ERJ-1GNJ123C" 0201 2633.98,1510.29 r0 top value="12 kΩ"
SH-J12 "SPC02SYAN" SPC02SYAN 2730,1890 r180 top value=1x2
SH-J13 "HMSC-G" HMSC-G 2005,1425 r135 top value=1x2
SW1 "500ASSP1M2QE" 500ASSP1M2QE 1088.81,298.32 r270 top
SW2 "cmp00353" 450301014042 107.48,1815 r270 top
SW3 "cmp00353" 450301014042 2848.45,98.72 r180 top
SW4 "FSMSM" FSMSM 1563.61,529.61 r90 top
SW5 "CHS-02TA" CHS-02TA 1742.52,1690.49 r45 top
T1 "ADT1-1WT+" CD542 1681.11,1233.05 r0 top
T2 "ADT1-6T+" CD637 2138.45,618.72 r0 top
T3 "ADT1-6T+" CD637 2137.46,1878.88 r180 top
TP1 "5010" Keystone5010 786.05,648 r0 top
TP2 "5125" Keystone5125 466.33,700.79 r0 top
TP3 "5116" KEYSTONE5116 1984.19,1030.26 r90 top
U1 "ADC3644IRSB" RSB0040E 2185.69,1248.8 r0 top
U2 "TPS259261DRC" DRC0010J 1201.22,353.52 r90 bottom
U3 "TPS82140SILR" SIL0008D 1052.5,682.49 r90 bottom
U4 "TPSM82913RDU" RDU0028A 169.58,991.3 r0 bottom
U5 "INA180B1IDBVR" DBV0005A 909.65,1588.15 r0 bottom
U6 "TPS7A9601DSC" DRC0010J 617.53,1532.05 r0 top
U7 "INA180B1IDBVR" DBV0005A 909.65,1188.15 r0 bottom
U8 "TPS7A9601DSC" DRC0010J 617.53,1132.05 r0 top
U9 "ADS1119IRTER" RTE0016D 1278.89,1948.29 r180 bottom
U10 "SN74LVC2G125DCUT" DCU0008A 728.86,2203.24 r270 bottom
U11 "FT4232HL-REEL" LQFP64-MFG 689.49,2217.81 r0 top locked
U12 "93LC46B-I/ST" TSSOP-8 595,2221.75 r270 bottom
U13 "TMUX1136DGS" DQA0010A 1245.41,2323.6 r0 bottom
U14 "SN74AVC4T774BQB" BQB0016A-MFG 1054.25,2162.51 r0 bottom
U15 "SN74CBTLV3257RSV" RSV0016A 1226.77,2162.51 r90 bottom
U16 "SN74LVC1G125DRL" DRL0005A 1330.31,2095.1 r90 bottom
U17 "TMUX136RSE" RSE0010A 2633.64,854.8 r180 top
U18 "TPS3125J18DBVR" DBV0005A 1563.61,576.69 r270 bottom
U19 "SN74AUP1G08DCKT" DCK0005A 1563.61,408.64 r0 bottom
U20 "REF35160QDBV" DBV0006A 1926.24,1554.52 r315 bottom
U21 "24LC64FT-I/MNY" TDFN8 3260,254.52 r180 top
U22 "SN74AUCH16244DGG" DGG0048A 2757.64,1258.64 r180 bottom locked
U23 "SN74LVC1G125DRL" DRL0005A 1064.05,2419.8 r180 bottom
Y1 "ABM3-12.000MHZ-D2Y-T" XTAL_ABM3 403.18,2522.22 r45 top
ZZ1 "These assemblies are ESD sensitive, ESD precautions shall be observed." AssemblyNote 294.17,3050 r0 top

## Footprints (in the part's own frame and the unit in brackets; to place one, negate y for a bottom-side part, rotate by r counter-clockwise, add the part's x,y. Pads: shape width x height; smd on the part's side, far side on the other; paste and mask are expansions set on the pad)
0201 [mm] "Data from Kemet datasheet CC101_COM dated 7/28/11"
  rrect20% 0.36x0.32 smd mask+0.051: 1(-0.28,0) 2(0.28,0)
  body extent -0.31,-0.16 0.31,0.16, height 0.26
0201_cap [mm] "Data from Kemet datasheet CC101_COM dated 7/28/11"
  rrect20% 0.36x0.32 smd mask+0.051: 1(-0.28,0) 2(0.28,0)
  body extent -0.31,-0.16 0.31,0.16, height 0.26
0402L#1 [mm] "0402 from SM-752 data"
  rect 0.6x0.5 smd: 1(-0.5,0) 2(0.5,0)
  body extent -0.55,-0.3 0.55,0.3, height 0.6
0402L#2 [mm] "0402 from SM-752 data"
  rrect20% 0.6x0.5 smd mask+0.051: 1(-0.5,0) 2(0.5,0)
  body extent -0.55,-0.3 0.55,0.3, height 0.6
0402L_cap#1 [mm] "0402 from SM-752 data"
  rrect20% 0.6x0.5 smd mask+0.051: 1(-0.5,0) 2(0.5,0)
  body extent -0.55,-0.3 0.55,0.3, height 0.6
0402L_cap#2 [mm] "0402 from SM-752 data"
  rect 0.6x0.5 smd: 1(-0.5,0) 2(0.5,0)
  body extent -0.55,-0.3 0.55,0.3, height 0.6
500ASSP1M2QE [mm]
  rect 1.635x1.635 hole 1.09: 1(-2.54,0)
  round 1.635 hole 1.09: 2(0,0) 3(2.54,0)
  silkscreen extent -5.08,-2.54 5.08,2.54, body extent -5.08,-2.54 5.08,2.54, height 13.32
0603L [mm] "0603 from SM-752 data"
  rrect20% 0.8x0.85 smd: 1(-0.7,0) 2(0.7,0)
  silkscreen extent -0.07,-0.33 0.07,0.33, body extent -0.87,-0.47 0.87,0.47, height 1
0603L_cap [mm] "0603 from SM-752 data"
  rrect20% 0.8x0.85 smd: 1(-0.7,0) 2(0.7,0)
  silkscreen extent -0.07,-0.33 0.07,0.33, body extent -0.87,-0.47 0.87,0.47, height 1
0805L [mm] "0805 from SM-752 data"
  rrect20% 1.1x1.4 smd: 1(-0.75,0) 2(0.75,0)
  body extent -1,-0.62 1,0.63, height 0.7
0805L_cap [mm] "0805 from SM-752 data"
  rrect20% 1.1x1.4 smd: 1(-0.75,0) 2(0.75,0)
  body extent -1.1,-0.72 1.1,0.72, height 1.45
450301014042 [mm]
  round 1.65 hole 1.016: 1(0,0) 2(-2.54,0)
  rect 1.65x1.65 hole 1.016: 3(2.54,0)
  silkscreen extent -4.25,-1.3 4.25,1.3, body extent -4.98,-1.25 5.02,1.25, height 5.9
AssemblyNote [mil] "Assembly Note"
BQB0016A-MFG [mm]
  rrect42% 0.24x0.6 smd paste+0 mask+0.07: 1(-0.25,1.65) 8(-0.25,-1.65) 9(0.25,-1.65) 16(0.25,1.65)
  rrect42% 0.6x0.24 smd paste+0 mask+0.07: 2(-1.15,1.25) 3(-1.15,0.75) 4(-1.15,0.25) 5(-1.15,-0.25) 6(-1.15,-0.75) 7(-1.15,-1.25) 10(1.15,-1.25) 11(1.15,-0.75) 12(1.15,-0.25) 13(1.15,0.25) 14(1.15,0.75) 15(1.15,1.25)
  round 0.454 hole 0.2 mask+0.05: 17(0,-0.75) 17(0,0.75)
  rrect10% 1x2 smd paste-1000 mask+0.07: 17(0,0)
  silkscreen extent -1.67,-1.8 1.3,1.8, body extent -1.25,-1.75 1.25,1.75, height 0.8
cbts130a [mm]
  round 5.5 hole 3.4 paste-2539.97 mask+0: ""(0,0)
  body extent -3.18,-2.75 3.18,2.75, height 2.09
CCS0603FLxLxx [mm]
  rrect33% 1.41x0.92 smd: 1(-0.9,0) 2(0.89,0)
  body extent -0.93,-0.52 0.93,0.52, height 0.66
CD542 [mil]
  rrect6% 100x65 smd paste+0 mask+2.76: 1(-100,100) 2(-100,0) 3(-100,-100) 4(100,-100) 5(100,0) 6(100,100)
  silkscreen extent -183,-158 112,158, body extent -154,-161 154,161, height 10
CD637 [mil]
  rrect6% 65x100 smd paste+0 mask+0: 1(-100,-100) 2(0,-100) 3(100,-100) 4(100,100) 5(0,100) 6(-100,100)
  silkscreen extent -158,-184 158,112, body extent -161,-154 161,154, height 10
CE_Mark_5mm [mil] "Minimum text height for CE Mark"
  silkscreen extent -138,-98 138,98
CHS-02TA [mm]
  rrect50% 0.76x1.6 smd mask+0.07: 1(-0.635,2.54) 2(0.635,2.54) 3(0.635,-2.54) 4(-0.635,-2.54)
  silkscreen extent -1.47,2.73 -1.33,2.87, body extent -2.03,-2.8 2.03,2.8, height 2.5
DBV0005A [mm] "SOT23, 5-Leads, Body 2.9x1.6mm, Pitch 0.95mm, Lead Span 2.8mm, IPC High Density"
  rrect18% 1.1x0.6 smd mask+0.07: 1(-1.3,0.95) 2(-1.3,0) 3(-1.3,-0.95) 4(1.3,-0.95) 5(1.3,0.95)
  silkscreen extent -0.35,-1.55 0.35,1.55, body extent -1.42,-1.46 1.42,1.46, height 1.09
DBV0006A [mm] "SOT23, 6-Leads, Body 2.9x1.6mm, Pitch 0.95mm, Lead Span 2.8mm, IPC High Density"
  rrect18% 1.1x0.6 smd mask+0.07: 1(-1.3,0.95) 2(-1.3,0) 3(-1.3,-0.95) 4(1.3,-0.95) 5(1.3,0) 6(1.3,0.95)
  silkscreen extent -0.35,-1.55 0.35,1.55, body extent -1.5,-1.5 1.5,1.5, height 1.3
DCK0005A [mm] "SOT353, 5-Leads, Body 2x1.3mm, Pitch 0.65mm, Lead Span 2.1mm, IPC High Density"
  rrect25% 0.9x0.4 smd mask+0.05: 1(-1.1,0.65) 2(-1.1,0) 3(-1.1,-0.65) 4(1.1,-0.65) 5(1.1,0.65)
  silkscreen extent -0.25,-1.1 0.25,1.1, body extent -1.14,-1 1.14,1, height 0.95
DCU0008A [mm] "TSSOP, 8-Leads, Body 2x2.3mm, Pitch 0.5mm, IPC High Density"
  rrect30% 0.8x0.3 smd mask+0.05: 1(-1.55,0.75) 2(-1.55,0.25) 3(-1.55,-0.25) 4(-1.55,-0.75) 5(1.55,-0.75) 6(1.55,-0.25) 7(1.55,0.25) 8(1.55,0.75)
  silkscreen extent -1.05,-1.05 0.38,1.05, body extent -1.56,-1 1.56,1, height 0.9
DGG0048A [mm]
  rrect30% 1.5x0.3 smd mask+0.05: 1(-3.75,5.75) 2(-3.75,5.25) 3(-3.75,4.75) 4(-3.75,4.25) 5(-3.75,3.75) 6(-3.75,3.25) 7(-3.75,2.75) 8(-3.75,2.25) 9(-3.75,1.75) 10(-3.75,1.25) 11(-3.75,0.75) 12(-3.75,0.25) 13(-3.75,-0.25) 14(-3.75,-0.75) 15(-3.75,-1.25) 16(-3.75,-1.75) 17(-3.75,-2.25) 18(-3.75,-2.75) 19(-3.75,-3.25) 20(-3.75,-3.75) 21(-3.75,-4.25) 22(-3.75,-4.75) 23(-3.75,-5.25) 24(-3.75,-5.75) 25(3.75,-5.75) 26(3.75,-5.25) 27(3.75,-4.75) 28(3.75,-4.25) 29(3.75,-3.75) 30(3.75,-3.25) 31(3.75,-2.75) 32(3.75,-2.25) 33(3.75,-1.75) 34(3.75,-1.25) 35(3.75,-0.75) 36(3.75,-0.25) 37(3.75,0.25) 38(3.75,0.75) 39(3.75,1.25) 40(3.75,1.75) 41(3.75,2.25) 42(3.75,2.75) 43(3.75,3.25) 44(3.75,3.75) 45(3.75,4.25) 46(3.75,4.75) 47(3.75,5.25) 48(3.75,5.75)
  silkscreen extent -4.22,-6.25 3.05,6.3, body extent -4.06,-6.25 4.06,6.25, height 1.1
DQA0010A [mm] "SON, 10-Leads, Body 1x2.5mm, Pitch 0.5mm, TI Recommended"
  rrect50% 0.565x0.2 smd mask+0.07: 1(-0.417,1) 2(-0.417,0.5) 4(-0.417,-0.5) 5(-0.417,-1) 6(0.417,-1) 7(0.417,-0.5) 9(0.417,0.5) 10(0.417,1)
  rrect28% 0.565x0.36 on Bottom Paste mask+0.07: 3(-0.417,0) 8(0.417,0)
  rrect25% 0.565x0.4 smd paste-0.2 mask+0.07: 3(-0.417,0) 8(0.417,0)
  silkscreen extent -0.67,-1.45 0.55,1.45, body extent -0.5,-1.25 0.5,1.25, height 0.55
DQK0006C [mm] "WSON"
  rrect12% 0.9x0.86 on Bottom Paste: 0(0,0.325)
  rrect34% 0.7x0.29 on Bottom Paste: 0(0.095,-0.65)
  rrect33% 0.45x0.3 smd: 1(-0.975,0.65) 2(-0.975,0) 3(-0.975,-0.65) 4(0.975,-0.65) 5(0.975,0) 6(0.975,0.65)
  rrect33% 0.75x0.3 smd paste-0.15: 7(0.095,-0.65)
  rrect11% 1x0.95 smd paste-0.5: 8(0,0.325)
  silkscreen extent -1.15,-1.15 1.15,1.15, body extent -1,-1 1,1, height 0.75
DRC0010J [mm] "VSON-10"
  rrect42% 0.6x0.24 smd mask+0.07: 1(-1.4,1) 2(-1.4,0.5) 3(-1.4,0) 4(-1.4,-0.5) 5(-1.4,-1) 6(1.4,-1) 7(1.4,-0.5) 8(1.4,0) 9(1.4,0.5) 10(1.4,1)
  round 0.454 hole 0.2 mask+0.05: 11(-0.575,0) 11(0,-0.95) 11(0,0.95) 11(0.575,0)
  round 0.025 smd mask+0.07: 11(0,0)
  Top Layer region: -0.375,-1.65 -0.375,-1.2 -0.775,-1.2 -0.794,-1.196 -0.81,-1.185 -0.821,-1.169 -0.825,-1.15 -0.825,-1.15 -0.825,1.15 -0.821,1.169 -0.81,1.185 -0.794,1.196 -0.775,1.2 -0.775,1.2 -0.375,1.2 -0.375,1.65 -0.371,1.669 -0.36,1.685 -0.344,1.696 -0.325,1.7 -0.325,1.7 -0.325,1.7 -0.175,1.7 -0.175,1.7 -0.156,1.696 -0.14,1.685 -0.129,1.669 -0.125,1.65 -0.125,1.65 -0.125,1.2 0.125,1.2 0.125,1.65 0.129,1.669 0.14,1.685 0.156,1.696 0.175,1.7 0.175,1.7 0.175,1.7 0.325,1.7 0.325,1.7 0.344,1.696 0.36,1.685 0.371,1.669 0.375,1.65 0.375,1.65 0.375,1.2 0.775,1.2 0.794,1.196 0.81,1.185 0.821,1.169 0.825,1.15 0.825,1.15 0.825,-1.15 0.821,-1.169 0.81,-1.185 0.794,-1.196 0.775,-1.2 0.775,-1.2 0.375,-1.2 0.375,-1.65 0.371,-1.669 0.36,-1.685 0.344,-1.696 0.325,-1.7 0.325,-1.7 0.175,-1.7 0.156,-1.696 0.14,-1.685 0.129,-1.669 0.125,-1.65 0.125,-1.65 0.125,-1.2 -0.125,-1.2 -0.125,-1.65 -0.129,-1.669 -0.14,-1.685 -0.156,-1.696 -0.175,-1.7 -0.175,-1.7 -0.325,-1.7 -0.344,-1.696 -0.36,-1.685 -0.371,-1.669 -0.375,-1.65
  silkscreen extent -1.97,0.95 -1.84,1.08, body extent -1.5,-1.5 1.5,1.5, height 1
DRL0005A [mm] "SOTFL, 5-Flat Leads, Body 1.2x1.6x0.6mm, Pitch 0.5mm, TI recommended"
  rrect33% 0.67x0.3 smd mask+0.05: 1(-0.74,0.5) 2(-0.74,0) 3(-0.74,-0.5) 4(0.74,-0.5) 5(0.74,0.5)
  silkscreen extent -0.9,-0.95 0.5,0.95, body extent -0.8,-0.8 0.8,0.8, height 0.6
ESD_Overlay_Small [mil]
  silkscreen extent -62,-48 64,61
FCC_disclaimer [mil]
FDL_Small [mil]
  silkscreen extent -54,-32 54,73
Fiducial10-20 [mm]
  round 1 smd paste-0.508 mask+0.203: 1(0,0)
FIL_BNX002-11 [mm]
  rect 1.8x1.8 hole 1.2: 1(2.5,2.5)
  round 1.8 hole 1.2: 2(2.5,-2.5) 3(-2.5,2.5) 4(-2.5,-2.5) 4(0,0) 4(5,0)
  silkscreen extent -6,-5.5 6,6.35, body extent -6,-5.5 6,5.5, height 13
FP-132134-15_CONN_SMA_JACK-MFG [mm]
  round 0.864 smd paste+0 mask+0: 1(0,0)
  round 2.6 hole 1.7 paste-2539.97 mask+0: 2(-2.54,2.54) 3(2.54,2.54) 4(-2.54,-2.54) 5(2.54,-2.54)
  silkscreen extent -3.6,-3.6 3.6,3.6, body extent -3.94,-3.94 3.94,3.94, height 0.25
FP-USB4105-GF-A_CONN_USB_9MM58_7MM53-MFG [mm]
  rrect100% 1x2.1 hole 1.7 slot 0.6 at 0 deg paste-2539.97 mask+0: 1(-4.32,3.015) 2(4.32,3.015)
  rrect100% 1x1.8 hole 1.4 slot 0.6 at 0 deg paste-2539.97 mask+0: 3(-4.32,-1.165) 4(4.32,-1.165)
  rrect17% 0.6x1.15 smd paste+0 mask+0: A1(-3.2,3.59) A4(-2.4,3.59) B1(3.2,3.59) B4(2.4,3.59)
  rrect33% 0.3x1.15 smd paste+0 mask+0: A5(-1.25,3.59) A6(-0.25,3.59) A7(0.25,3.59) A8(1.25,3.59) B5(1.75,3.59) B6(0.75,3.59) B7(-0.75,3.59) B8(-1.75,3.59)
  round 0.65 hole 0.65 unplated paste-2539.97 mask+0: ""(-2.89,2.515) ""(2.89,2.515)
  silkscreen extent -4.86,0.11 4.86,4.84, body extent -4.96,-3.94 4.96,4.27, height 0.25
FSMSM [mm]
  rrect10% 2.2x1.6 smd: 1(-4.6,0) 2(4.6,0)
  body extent -5.54,-1.75 5.54,1.75, height 4.2
HDR_2x1_TH_VT_50mil [mil] "Sullins"
  rrect10% 41x41 hole 28: 1(-25,0)
  round 41 hole 28: 2(25,0)
  silkscreen extent -50,-42 50,53, body extent -50,-42 50,42, height 157
HMSC-G [mil]
  body extent -49,-30 49,30, height 160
